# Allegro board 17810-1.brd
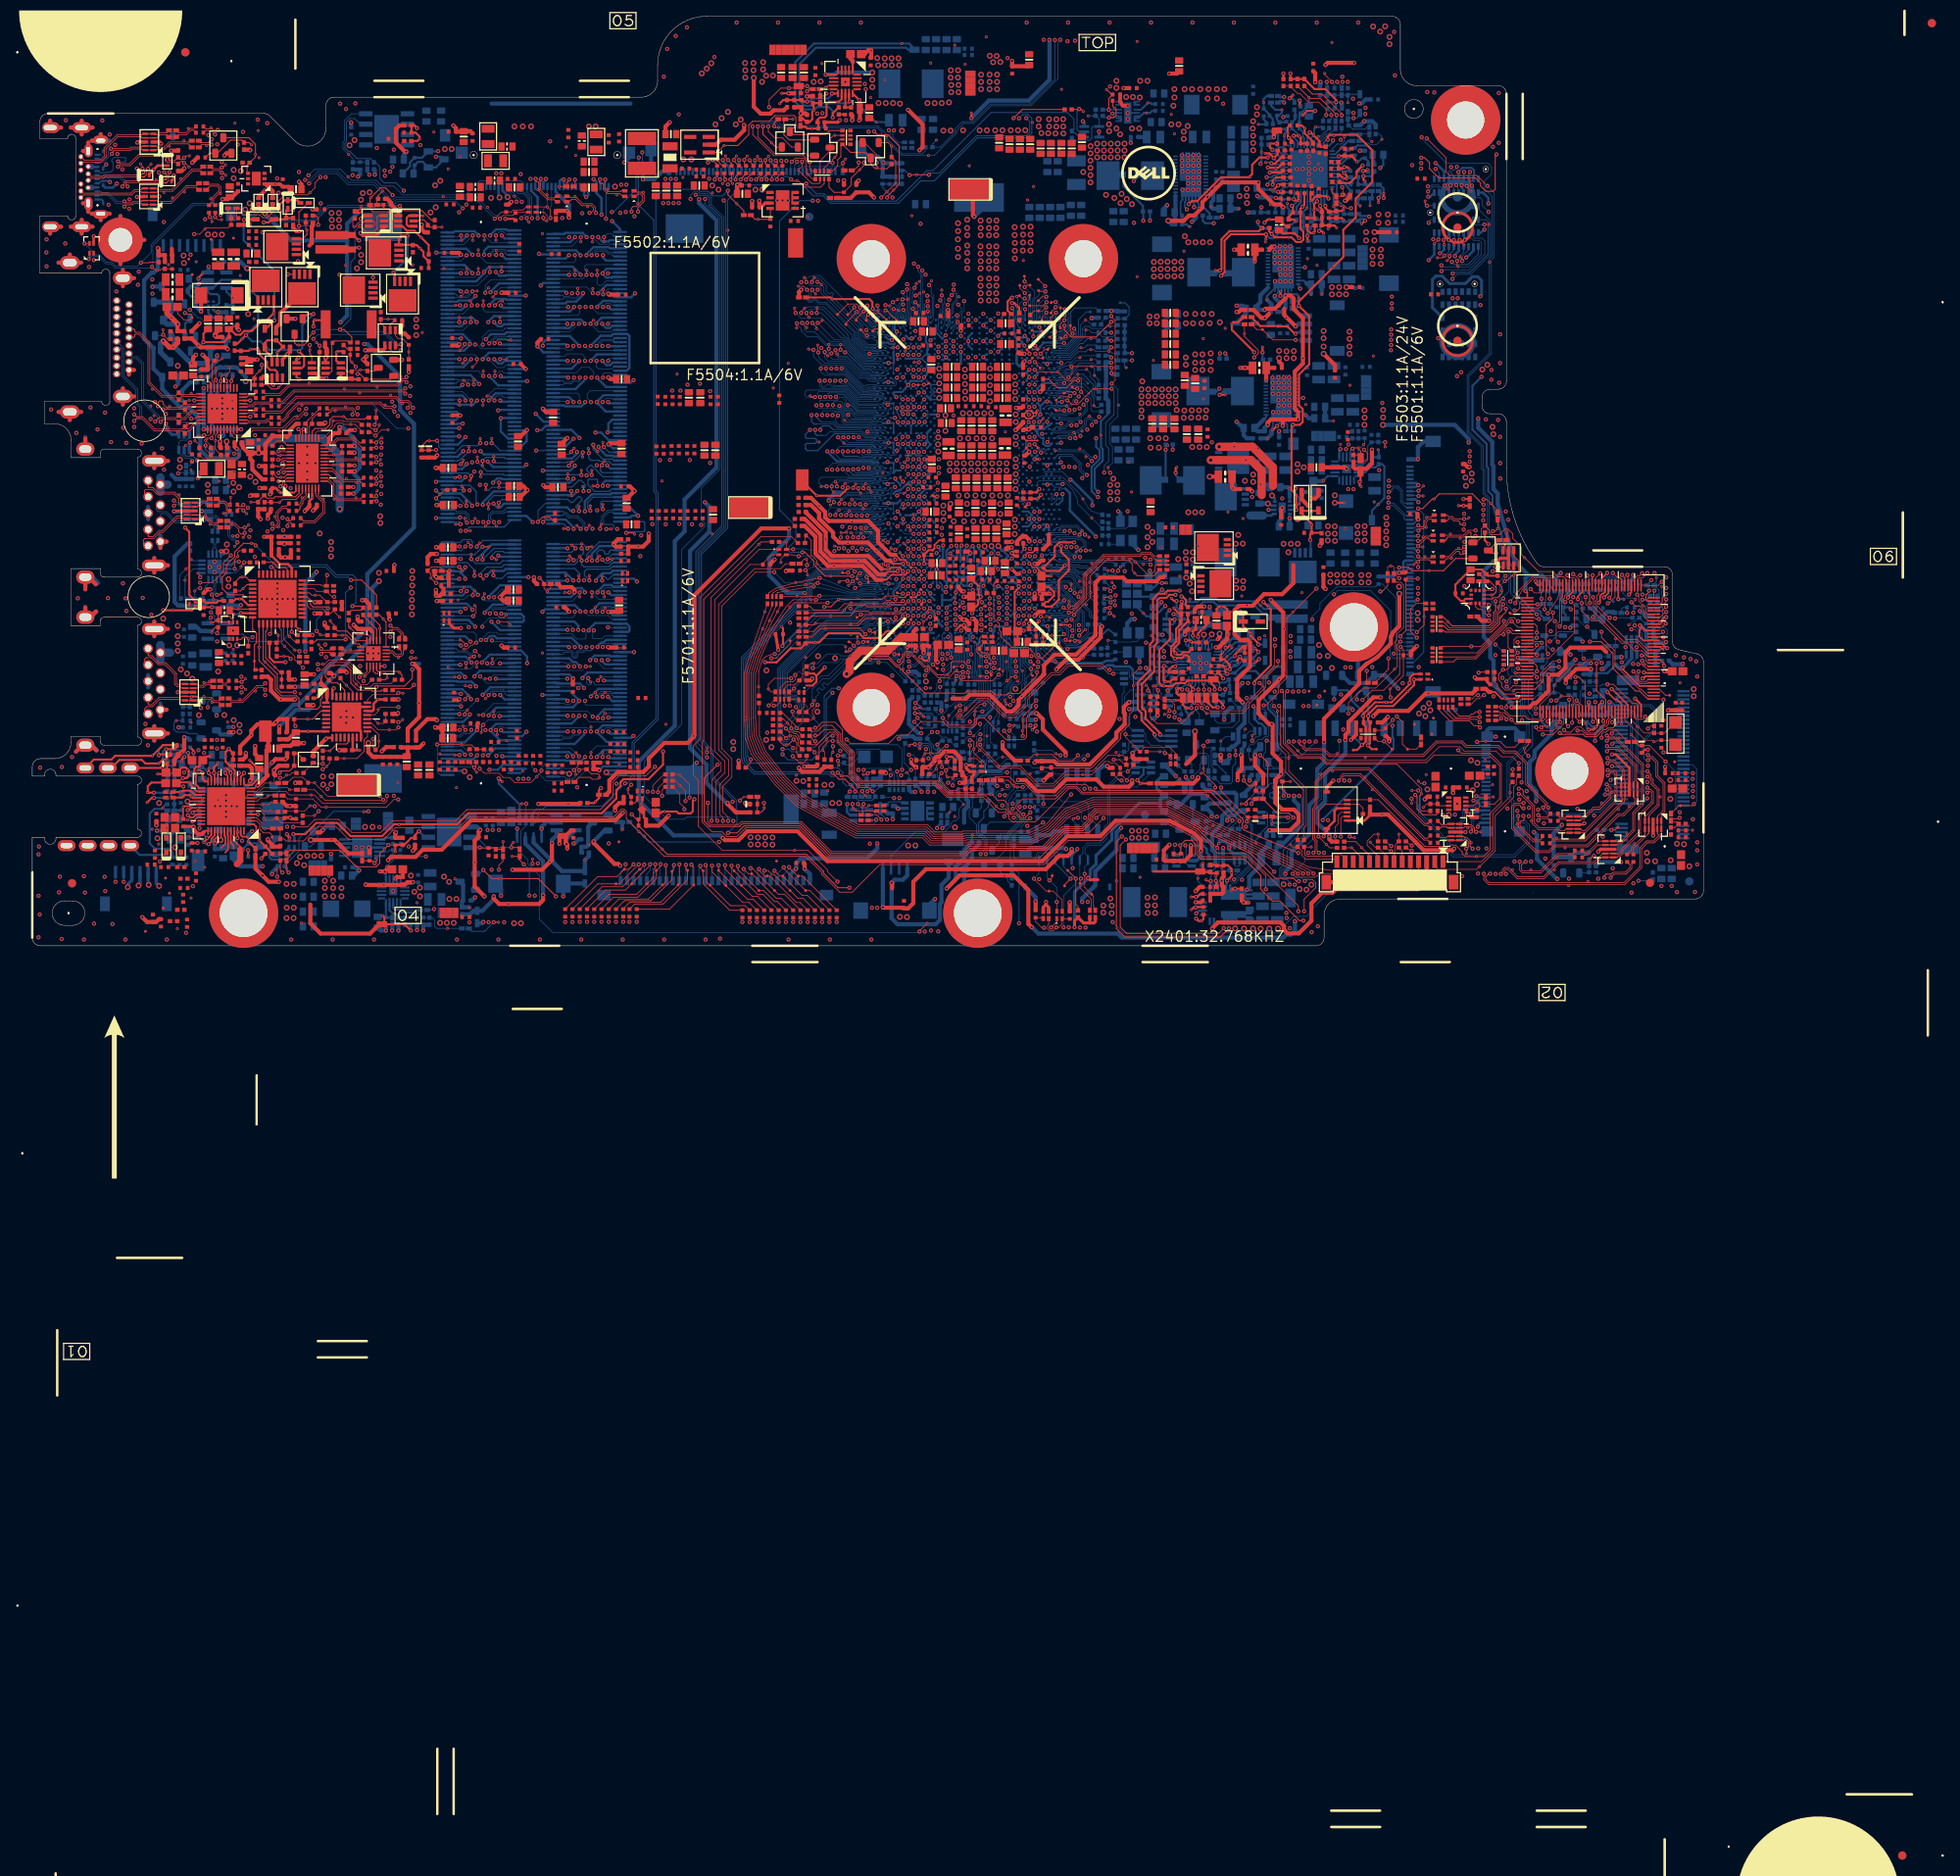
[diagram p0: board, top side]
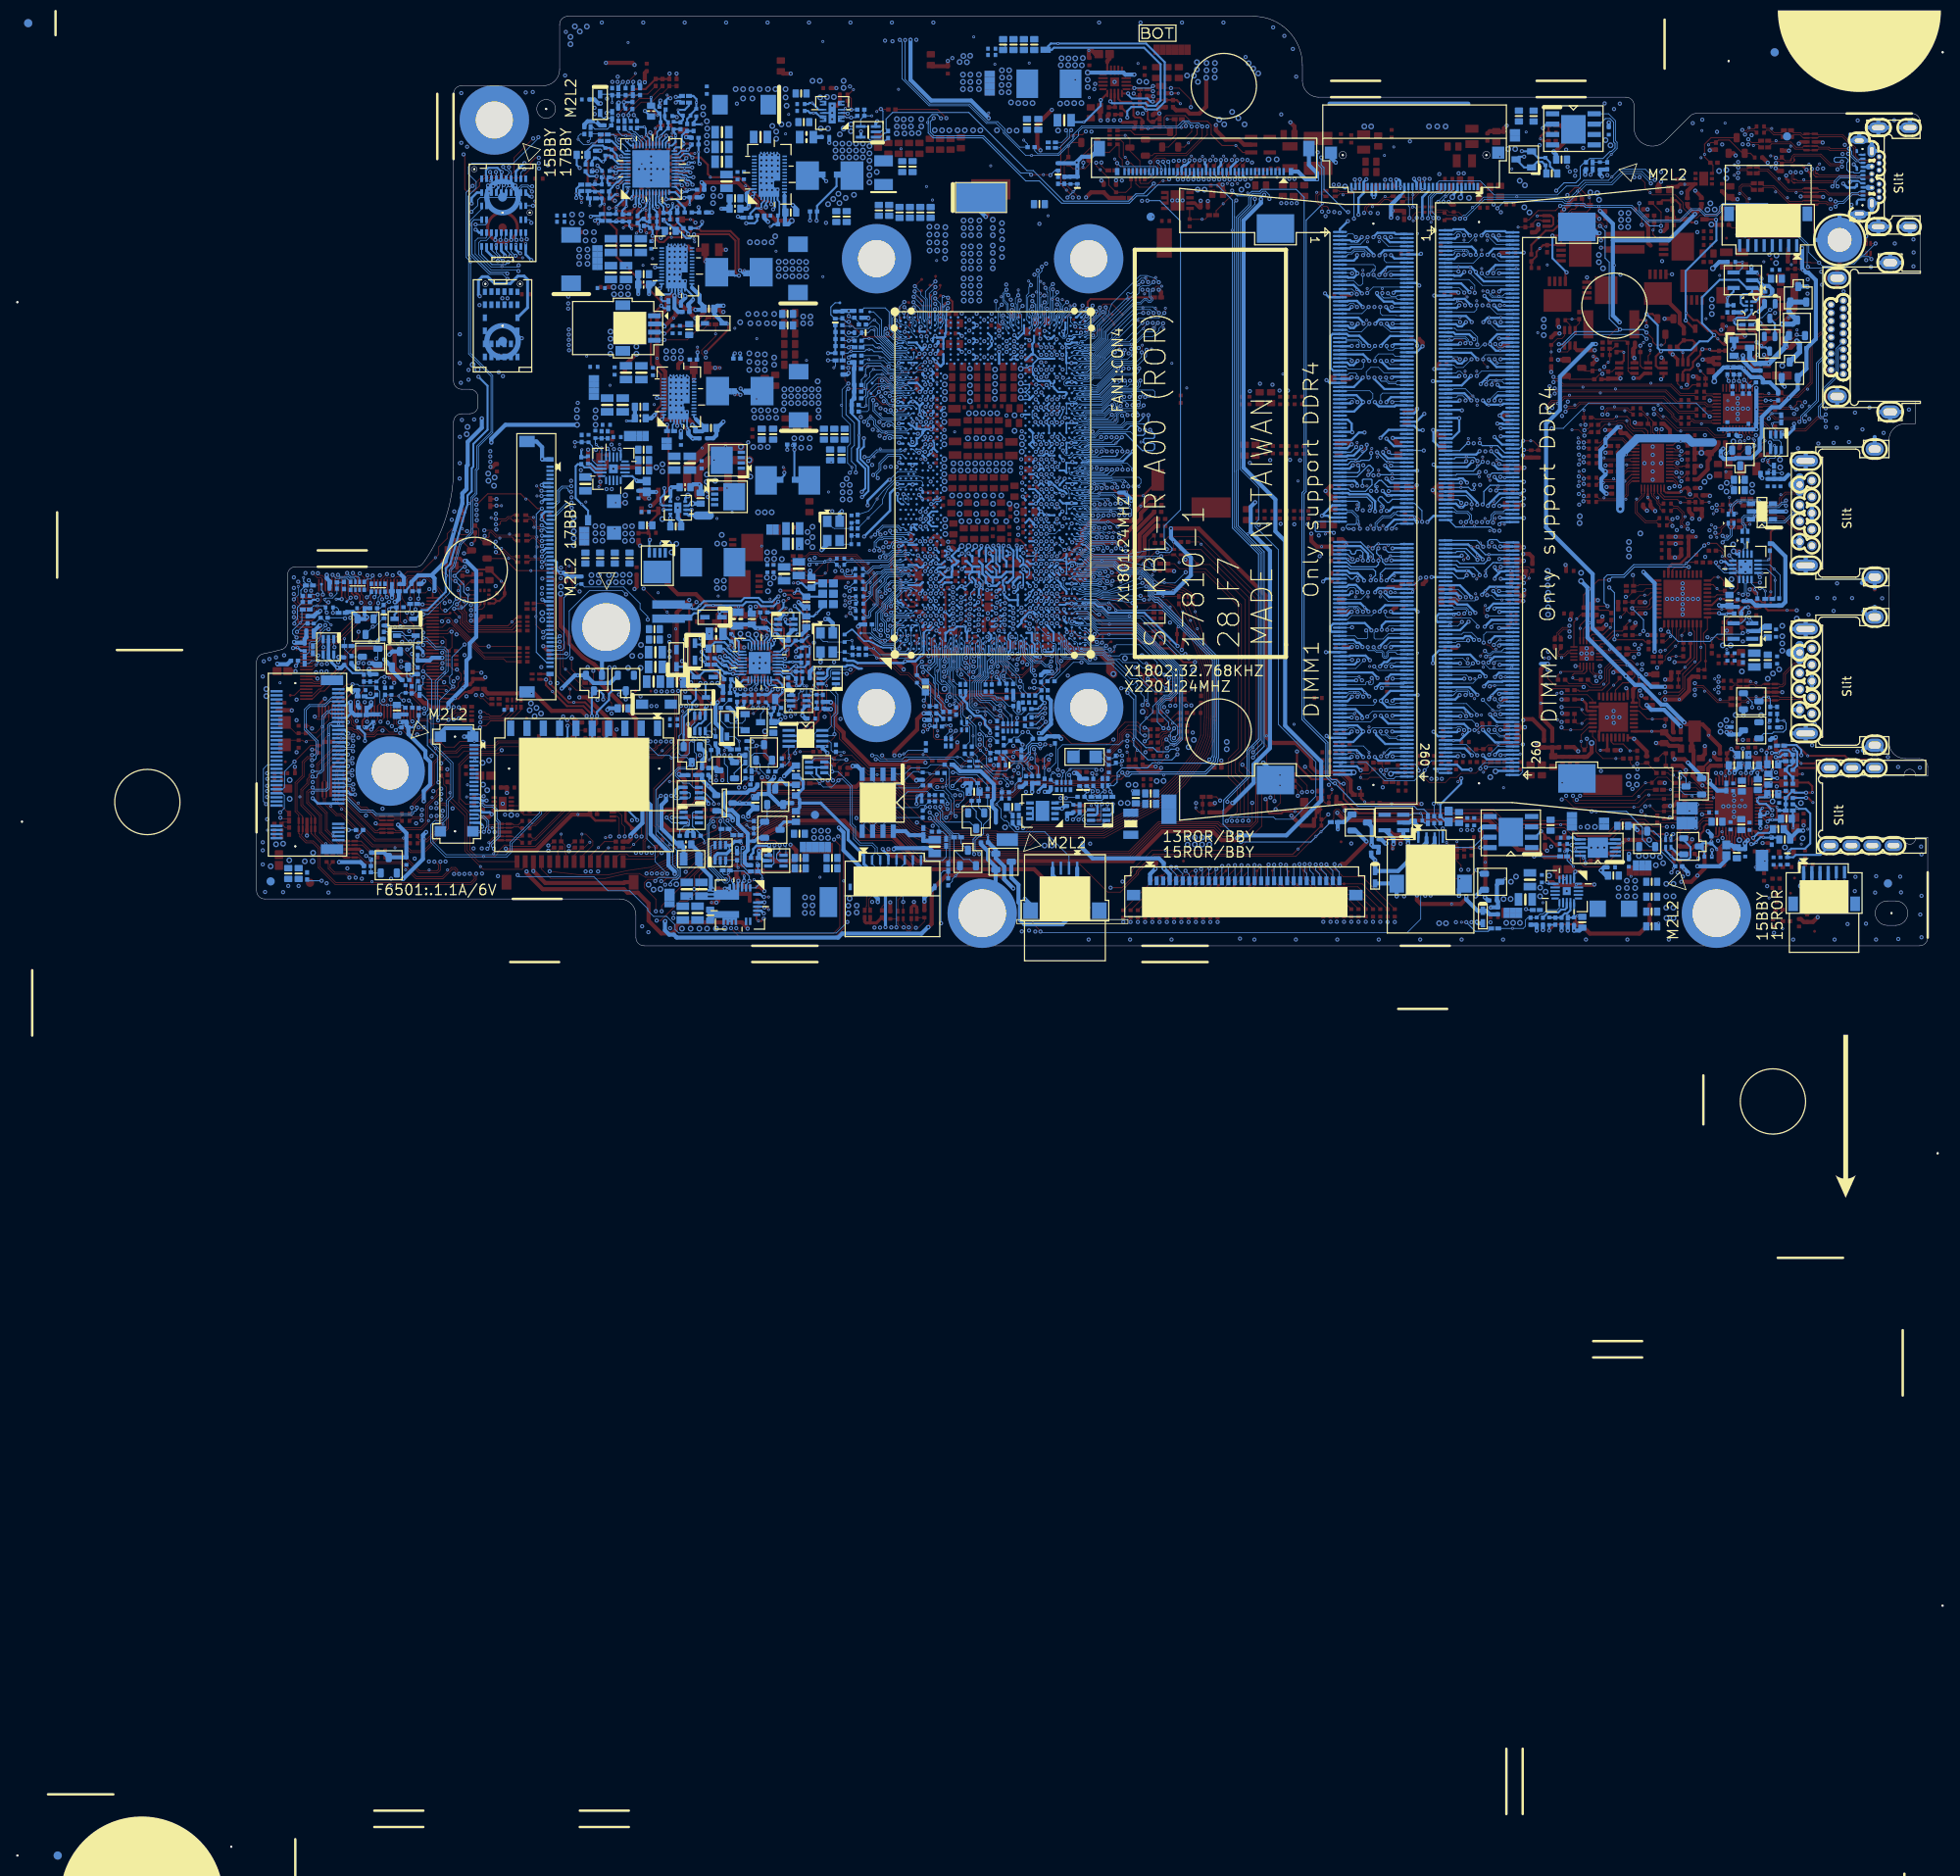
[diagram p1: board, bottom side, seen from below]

Outline 204.85 x 113.92 mm; copper layers: TOP, L2GND, L3, L4, L5VCC, L6, L7GND, BOTTOM. Coordinates in mm from the lower left corner of the outline.

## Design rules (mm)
constraint set DEFAULT: min track width 0.127, pair gap 0.102
net group CLK_50-MWS: nets SUS_CLK SUSCLK
net group CPU_RXN_C_DGPU_TXN0-DIFF1: nets CPU_RXN_C_DGPU_TXN0 CPU_RXP_C_DGPU_TXP0
net group CPU_RXN_C_DGPU_TXN1-DIFF1: nets CPU_RXN_C_DGPU_TXN1 CPU_RXP_C_DGPU_TXP1
net group CPU_RXN_C_DGPU_TXN2-DIFF1: nets CPU_RXN_C_DGPU_TXN2 CPU_RXP_C_DGPU_TXP2
net group CPU_RXN_C_DGPU_TXN3-DIFF1: nets CPU_RXN_C_DGPU_TXN3 CPU_RXP_C_DGPU_TXP3
net group DDR4_VREF_40: nets V_SM_VREF_CNTA V_SM_VREF_CNTB
net group DGPU_RXN_C_CPU_TXN0: nets DGPU_RXN_C_CPU_TXN0 PEG_TX_CPU_N0
net group DGPU_RXN_C_CPU_TXN1: nets DGPU_RXN_C_CPU_TXN1 PEG_TX_CPU_N1
net group DGPU_RXN_C_CPU_TXN2: nets DGPU_RXN_C_CPU_TXN2 PEG_TX_CPU_N2
net group DGPU_RXN_C_CPU_TXN3: nets DGPU_RXN_C_CPU_TXN3 PEG_TX_CPU_N3
net group DGPU_RXP_C_CPU_TXP0: nets DGPU_RXP_C_CPU_TXP0 PEG_TX_CPU_P0
net group DGPU_RXP_C_CPU_TXP1: nets DGPU_RXP_C_CPU_TXP1 PEG_TX_CPU_P1
net group DGPU_RXP_C_CPU_TXP2: nets DGPU_RXP_C_CPU_TXP2 PEG_TX_CPU_P2
net group DGPU_RXP_C_CPU_TXP3: nets DGPU_RXP_C_CPU_TXP3 PEG_TX_CPU_P3
net group EDP_AUX: nets EDP_AUX EDP_AUX_DP
net group EDP_AUX#: nets EDP_AUX# EDP_AUX_DN
net group ESPI_CLK: nets ESPI_CLK PCH_ESPI_CLK
net group ESPI_IO0: nets ESPI_IO0 PCH_ESPI_IO0
net group ESPI_IO1: nets ESPI_IO1 PCH_ESPI_IO1
net group ESPI_IO2: nets ESPI_IO2 PCH_ESPI_IO2
net group ESPI_IO3: nets ESPI_IO3 PCH_ESPI_IO3
net group FAN_TACH: nets FAN1_TACH FAN_TACH1_C
net group GPU_THM_SMBCLK: nets GPU_THM_SMBCLK THM_SML1_CLK
net group GPU_THM_SMBDAT: nets GPU_THM_SMBDAT THM_SML1_DATA
net group HDA_CODEC_SYNC: nets HDA_CODEC_SYNC HDA_SYNC
net group HDMI_CLK: nets HDMI_CLK HDMI_CLK_R
net group HDMI_CLK#: nets HDMI_CLK# HDMI_CLK#_R
net group HDMI_DATA0: nets HDMI_DATA0 HDMI_DATA0_R
net group HDMI_DATA0#: nets HDMI_DATA0# HDMI_DATA0#_R
net group HDMI_DATA1: nets HDMI_DATA1 HDMI_DATA1_R
net group HDMI_DATA1#: nets HDMI_DATA1# HDMI_DATA1#_R
net group HDMI_DATA2: nets HDMI_DATA2 HDMI_DATA2_R
net group HDMI_DATA2#: nets HDMI_DATA2# HDMI_DATA2#_R
net group I2C0_SCL_R: nets I2C0_SCL_R I2C0_SCL_TCH_PAD
net group I2C0_SDA_R: nets I2C0_SDA_R I2C0_SDA_TCH_PAD
net group MEM_SMBCLK: nets MEM_SMBCLK PCH_SMBCLK
net group MEM_SMBDATA: nets MEM_SMBDATA PCH_SMBDATA
net group MUX_TYPEC_TXN1: nets MUX_TYPEC_TXN1 MUX_TYPEC_TXN1_C
net group MUX_TYPEC_TXN2: nets MUX_TYPEC_TXN2 MUX_TYPEC_TXN2_C
net group MUX_TYPEC_TXP1: nets MUX_TYPEC_TXP1 MUX_TYPEC_TXP1_C
net group MUX_TYPEC_TXP2: nets MUX_TYPEC_TXP2 MUX_TYPEC_TXP2_C
net group PCH_DPC_N0: nets PCH_DPC_N0 PCH_DPC_N0_C
net group PCH_DPC_N1: nets PCH_DPC_N1 PCH_DPC_N1_C
net group PCH_DPC_N2: nets PCH_DPC_N2 PCH_DPC_N2_C
net group PCH_DPC_N3: nets PCH_DPC_N3 PCH_DPC_N3_C
net group PCH_DPC_P0: nets PCH_DPC_P0 PCH_DPC_P0_C
net group PCH_DPC_P1: nets PCH_DPC_P1 PCH_DPC_P1_C
net group PCH_DPC_P2: nets PCH_DPC_P2 PCH_DPC_P2_C
net group PCH_DPC_P3: nets PCH_DPC_P3 PCH_DPC_P3_C
net group PCIE_RCOMP-DIFF: nets PCIE_RCOMPN PCIE_RCOMPP
net group PCIE_TX_CPU_N6: nets PCIE_TX_CPU_N6 PCIE_TX_WLAN_N6
net group PCIE_TX_CPU_N9: nets PCIE_TX_CPU_N9 PCIE_TX_CPU_N9_C
net group PCIE_TX_CPU_N10: nets PCIE_TX_CPU_N10 PCIE_TX_CPU_N10_C
net group PCIE_TX_CPU_N11: nets PCIE_TX_CPU_N11 PCIE_TX_CPU_N11_C
net group PCIE_TX_CPU_P6: nets PCIE_TX_CPU_P6 PCIE_TX_WLAN_P6
net group PCIE_TX_CPU_P9: nets PCIE_TX_CPU_P9 PCIE_TX_CPU_P9_C
net group PCIE_TX_CPU_P10: nets PCIE_TX_CPU_P10 PCIE_TX_CPU_P10_C
net group PCIE_TX_CPU_P11: nets PCIE_TX_CPU_P11 PCIE_TX_CPU_P11_C
net group PEG_CLK_CPU0-DIFF1: nets CLK_PCIE_VGA CLK_PCIE_VGA#
net group PEG_CLK_CPU1-DIFF221: nets PEG_CLK1_CPU PEG_CLK1_CPU#
net group POWER_120MIL: nets +1.8VALW_EC +VCCSTG
net group SATA_TX_CPU_N12: nets SATA_TX_CPU_N12 SATA_TX_CPU_N12_C
net group SATA_TX_CPU_P12: nets SATA_TX_CPU_P12 SATA_TX_CPU_P12_C
net group SIGNAL_V_F_8_OHM-MW: nets CFG3 XDP_DBRESET#
net group SIGNAL_V_F_16.5_SVID-MWS: nets VR_SVID_CLK VR_SVID_DATA
net group SPI_CS_CPU_N0: nets SPI_CS_CPU_N0 SPI_CS_ROM_N0
net group USB30_RX_C2-DIFF242: nets USB30_RXDN2_C USB30_RXDP2_C
net group USB30_RX_CPU_N4: nets USB30_RX_CPU_N4 USB30_RX_CPU_N4_C
net group USB30_RX_CPU_P4: nets USB30_RX_CPU_P4 USB30_RX_CPU_P4_C
net group USB30_TX_CPU_N4: nets USB30_TX_CPU_N4 USB30_TX_CPU_N4_C
net group USB30_TX_CPU_P4: nets USB30_TX_CPU_P4 USB30_TX_CPU_P4_C
net group USB30_TXDN1_R: nets USB30_TX_CPU_N1 USB30_TXDN1_R
net group USB30_TXDN2_R: nets USB30_TX_CPU_N2 USB30_TXDN2_R
net group USB30_TXDP1_R: nets USB30_TX_CPU_P1 USB30_TXDP1_R
net group USB30_TXDP2_R: nets USB30_TX_CPU_P2 USB30_TXDP2_R
net group USB_CPU_PN0: nets USB_CPU_PN0 USB_PN0_R
net group USB_CPU_PP0: nets USB_CPU_PP0 USB_PP0_R
net group XDP_TCLK-MWS: nets XDP_TCK_JTAGX XDP_TCLK
net group XTAL24_IN: nets XTAL24_IN XTAL24_IN_R
net group XTAL24_IN_U42: nets XTAL24_IN_U42 XTAL24_IN_U42_R
net group XTAL24_OUT: nets XTAL24_OUT XTAL24_OUT_R
net group XTAL24_OUT_U42: nets XTAL24_OUT_U42 XTAL24_OUT_U42_R
net group XTAL-MW: nets MEC_XTAL1_R MEC_XTAL2
net group 3.5: nets CFG12 CFG14 M_A_DQS_DN0 M_A_DQS_DN1 M_A_DQS_DN2 M_A_DQS_DN3 M_A_DQS_DN4 M_A_DQS_DN5 M_A_DQS_DN6 M_A_DQS_DN7 M_A_DQS_DP0 M_A_DQS_DP1 M_A_DQS_DP2 M_A_DQS_DP3 M_A_DQS_DP4 M_A_DQS_DP5 M_A_DQS_DP6 M_A_DQS_DP7 M_B_DQS_DN1 M_B_DQS_DP1 USB_CPU_PN2 USB_CPU_PN4 USB_CPU_PN6 USB_CPU_PP2 USB_CPU_PP4 USB_CPU_PP6 VCCGT_SENSE VSSGT_SENSE
net group AUDIO_12MIL: nets CPVEE
net group AUDIO_BEEP_10MIL: nets AUD_HP1_JACK_L AUD_HP1_JACK_L1 AUD_HP1_JACK_R AUD_HP1_JACK_R1 AUD_PC_BEEP AUD_PC_BEEP_C AUD_PC_BEEP_R AUD_PORTA_L_R_B AUD_PORTA_R_R_B AUD_SENSE AUD_SENSE_A AUD_VREF CBN CBP HDA_SPKR_R JACK_PLUG JACK_PLUG_DET KBC_BEEP_R LINE1-L_C LINE1-L_R LINE1_L LINE1_R LINE1_VREFO_L LINE1_VREFO_R MIC2_VREFO_L MIC2_VREFO_R SPKR
net group AUDIO_DIGITAL_50-MWS: nets HDA_RST#
net group BOT_MUX_N: nets BOT_MUX_N_L
net group BOT_MUX_P: nets BOT_MUX_P_L
net group CCG4_MUX: nets 5V_VCONN_EN 5V_VCONN_P1 5V_VCONN_P1_CCG4 CCG4_FLIP# CCG4_OVP_TRIP_P1 CCG4_OVP_TRIP_P1_G DOCK_USB_EN_A DOCK_USB_EN_B MUX_ENA_L MUX_ENB_L MUX_INB_N MUX_INB_P MUX_SAI MUX_SAO MUX_SBI MUX_SBO VCONN_MON_P1
net group CFG_50-MWS: nets CFG0 CFG1 CFG2 CFG4 CFG5 CFG6 CFG7 CFG8 CFG9 CFG10 CFG11 CFG13 CFG15 CFG16 CFG17 CFG18 CFG19
net group CODEC_BITCLK_R: nets CODEC_BITCLK_R HDA_BITCLK HDA_CODEC_BITCLK
net group CODEC_SDOUT_R: nets CODEC_SDOUT_R HDA_CODEC_SDOUT HDA_SDOUT
net group COMP_20MIL: nets CPU_POPIRCOMP CSI2_COMP EMMC_RCOMP EOPIO_RCOMP PCH_POPIRCOMP SD_RCOMP SM_RCOMP_0 SM_RCOMP_1 SM_RCOMP_2 USBCOMP
net group CPU_50-MWS: nets H_PROCHOT#_R PQ4405_3 PWR_CHG_PROCHOT#
net group DDR4_A_CMD_40-MW: nets M_A_ALERT_N
net group DDR4_B_CMD_40--MW: nets M_B_ALERT_N
net group DPB_AUXN: nets DPB_AUXN_C
net group DPB_AUXP: nets DPB_AUXP_C
net group EDP_TX0: nets EDP_TX0
net group EDP_TX0#: nets EDP_TX0#
net group EDP_TX1: nets EDP_TX1
net group EDP_TX1#: nets EDP_TX1#
net group EDP_TX2: nets EDP_TX2
net group EDP_TX2#: nets EDP_TX2#
net group EDP_TX3: nets EDP_TX3
net group EDP_TX3#: nets EDP_TX3#
net group GND: nets MIC_GND
net group HDA_CODEC_SDIN0: nets HDA_CODEC_SDIN0
net group JTAG-MW: nets PCH_JTAG_TCK PCH_JTAG_TDI PCH_JTAG_TDO PCH_JTAG_TMS
net group KBC: nets KSI0 KSI1 KSI2 KSI3 KSI4 KSI5 KSI6 KSI7 KSO0 KSO1 KSO2 KSO3 KSO4 KSO5 KSO6 KSO7 KSO8 KSO9 KSO10 KSO11 KSO12 KSO13 KSO14 KSO15 KSO16
net group LCD_BKLT: nets BKLT_CTRL BKLT_EN_EC L_BKLT_CTRL L_BKLT_EN_EC LCD_BRIGHTNESS
net group LED: nets BAT1_LED# BAT2_LED# BATT_WHITE_LED# BATT_WHITE_LED_R# CAP_LED# CAP_LED_R# CHG_AMBER_LED#
net group LED_20MIL: nets AMBER_LED_BAT BAT_AMBER BAT_WHITE CAP_LED#_R CAP_LED_Q CHG_AMBER_LED_R# WHITE_LED_BAT
net group LPC-MWS: nets CLKRUN# CLKRUN#_EC ESPI_ALERT# ESPI_ALERT#_ESPI ESPI_CLK_C ESPI_IO0_C ESPI_IO1_C ESPI_IO2_C ESPI_IO3_C GPP_A10/CLKOUT_LPC1 LID_CL_SIO_TAB#
net group OTHER_4MIL: nets 1D8V_ESPI 3D_CAM_DET# A5_TP A67_TP A70_TP AD_IA AUX_EN_WOWL BLON_OUT BLON_OUT_C BLUETOOTH_EN BOARD_ID BOARD_ID1 BOARD_ID2 CAM_EN# CCG4_ID_1 CCG4_ID_2 CFG CLK_PCIE_LAN_REQ# CLK_PCIE_NVME_REQ# CLK_PCIE_PEG_REQ# CLK_PCIE_SD_REQ# CLK_PCIE_TBT_REQ# CLK_PCIE_WLAN_REQ# CMP_VIN1 COMBO-GPI CPU_DP1_HPD CPU_DP_HPD_MUX CTL1 CTL2 CTL3 DBC_EN_R DBC_PANEL_EN DCIN_EN DDCBUF DGPU_PWR_EN DGPU_PWROK DMIC_PCH_CLK DVSS EAPD# EDP_DISP_UTIL EDP_HPD EDP_HPD_CONN EQ FALL_INT2 FAN_PWM1_C FFS_INT2 FFS_INT2_Q FFS_INT2_Q_R GPD11/LANPHYPC GPIO052/SPI_IO2 GPP_E0/SATAXPCIE0/SATAGP0 GPP_E1/SATAXPCIE1/SATAGP1 GPU_PWR_LEVEL GSEN2_INT1_ISH GSEN2_INT2 GSEN2_INT2_ISH GSEN_INT1 GSEN_INT1_ISH GSEN_INT2 GSEN_INT2_ISH GYRO_DRDY_ISH GYRO_INT GYRO_INT_C GYRO_INT_ISH GYRO_INT_P11 H_CATERR# HDD_CT HDD_DET# HDD_DEVSLP_R HDD_EN HDD_EN_PCH HDMI_EC_DET# HDMI_EC_DET#_C HOST_DEBUG_TX HOST_DEBUG_TX_CON HPD_HDMI_CON HPD_HDMI_CON_C I2C0_SCL_TCH_PNL I2C0_SDA_TCH_PNL I_ADP_R ICSP_CLR IE_DELAY_G IE_DELAY_S ILIM_HI ILIM_LO ILIM_SEL INT2_SELECT INT#_TYPEC_R IR_CAM_DET# IR_CAMERA_DET#_R ISET ISH_KB_DISABLE ISH_KB_DISABLE_R KB_CLOSE#_2 KB_LED_BL_DET KB_LED_DET_C KBC_PWRBTN# L_BKLT_EN L_BKLT_EN_C LANWAKE# LCD_TST_C ME_FWP_EC MEM_CHB_EN MEM_CONFIG0 MODEL_ID MSATA_DEVSLP_R MSM# NB_MODE# NB_MUTE# NRB_BIT OVER_CURRENT_P8# P_SYS PBAT_PRES1# PBAT_PRES# PCH_BATLOW# PCH_THERMTRIP# PCH_WAKE# PCIE_WAKE# PD4403_A PD4403_K PD_VBUS_C_CTRL1_R PIRQA# PME# POWER_SW_IN# PQ4405_2 PQ4405_5 PQ4405_6 PQ4408_C PQ4408_E PRE PROC_SELECT# PROJECT_ID0 PROJECT_ID1 PROJECT_ID2 PROJECT_ID3 PS_ID_R PS_ID_R1 PSYS PWR_1D2V_EN PWR_2D5V_EN PWR_CHG_ACOK REXT SA0_CHA_DIM0 SA0_CHB_DIM0 SA1_CHA_DIM0 SA1_CHB_DIM0 SA2_CHA_DIM0 SA2_CHB_DIM0 SD_READ_MODE SERIRQ_TPM SIO_EXT_SMI# SIO_EXT_WAKE# SIO_PWRBTN# SIO_SLP_A# SIO_SLP_S5# SKTOCC# SLP_SUS# SM_INTRUDER# SMB_ALERT# SML0_ALERT# SML1ALERT# SPI_IRQ#_TPM2 SPK_ID SSD_DEVSLP SYS_PRES1# SYSPWR_PRES TOUCH_PAD_INTR# TOUCH_PANEL_PD# TP_WAKE_KBC# TPM_ID TPM_SPI_IRQ# USB2_ID USB2_VBUSSENSE USB_OC1# USB_OC2# USB_POWERSHARE_VBUS_EN USB_PWR_SHR_EN_L# VBUS_PRODECT# VCREF0 VOL_DOWN# VOL_UP# VR_RDY VRALERT# VRAM_ID1 VRAM_ID2 WIFI_RF_EN ZVM#
net group PECI-MW: nets H_PECI_CPU
net group PLATFORM: nets 1D0V_S5_PWRGD 1D8V_EN# 1D8V_EN_R# 1D8V_S5_PWROK 3D3V_S0_ON 3V5V_S0_ON 3V_5V_POK# 3V_5V_POK_C 5V_S0_ON +SDC_IN_SW +SDC_IN_SW_R1 CAD_SNK CPU_DP2_HPD CPU_DP_HPD CPU_DP_HPD_R DGPU_HOLD_RST# DPEQ0_A1 DPEQ1 EDP_VDD_EN EQ0 EQ1 GC6_FB_EN_MCP GPU_EVENT# GPU_EVENT_MCP# GSENSOR_CS GSENSOR_SDO H_CPUPWRGD H_VCCST_PWRGD HPDIN I2CEN IC_DELAY INT#_TYPEC LVDS_VDD_EN_R M2_SSD_PEDET ME_SUS_PWR_ACK_R PCH_PLTRST# PCH_RSMRST# PD_SWD_CLK PD_SWD_IO PD_VBUS_C_CTRL1 PD_VBUS_C_CTRL1_A PD_VBUS_DISCHG PD_VBUS_P_CTRL1 PD_VBUS_P_CTRL1_R PD_VBUS_R PD_VCCD PD_XRES PM_RSMRST#_M PM_RSMRST#_R PTP_DIS#_R PWR_0D6V_S3EN PWR_0D6V_S5EN PWR_0D6V_VCNTL PWR_1D0V_EN PWR_1D0V_PG PWR_1D5V_EN PWR_1D8V_EN PWR_1D8V_POK PWR_2D5V_PG PWR_3D3V_EN PWR_3D3V_EN1 PWR_3V_PG PWR_5V_PG PWR_VCORE_EN RSMRST_PWRGD# RTCRST_ON SATA_LED# SLP_LAN# SM_DRAMRST# SM_PGCNTL SM_PGCNTL_R SRTC_RST# SSD_PEDET SSEQ0_A0 SSEQ1 SUSACK#_R TP_ON#_GATE TPS70933_EN TPS70933_EN_G TS#_DIMM0_1 TS#_DIMM1_1 USB_ADT_SW USB_ADT_SW_R USB_EN# USB_TYPEC_R VCCSTG_EN_R VCCSTU_EN_R
net group POWER_10M: nets 1.8V_RUN_FB 3V5V_CT1 3V5V_CT2 5V_STB +3V_1D8V_AVDD +VCCAMPHYPLL_1P0 +VCCAPLL_1P0 +VCCCLK2 +VCCCLK4 +VCCCLK5 +VCCCOREG0 +VCCCOREG1 +VCCDSW_1P0 +VCCFUSEPRG +VCCPAZIO +VCCPDSW_3P3 +VCCPRTC_3P3 +VCCSFR +VCCST_CPU +VDDQ_CPU_CLK BOOST_MON I_BATT LDO1_CAP LDO2_CAP LDO3_CAP MIC_CAP PWR_1D0V_BT PWR_1D0V_FB PWR_1D0V_FB_A PWR_1D0V_PFM PWR_1D0V_SS PWR_1D0V_TON PWR_1D2V_BYP PWR_1D2V_IMAX PWR_1D2V_VFB PWR_1D2V_VFB_R PWR_2D5V_FB PWR_3D3V_FB PWR_3D3V_VOUT PWR_5V_EN PWR_5V_EN1 PWR_5V_EN1_R PWR_5V_FB PWR_5V_FB_A PWR_5V_LDO PWR_5V_VOUT PWR_VCCGT_COMP PWR_VCCGT_COMP_R PWR_VCCGT_CSCOMP PWR_VCCGT_CSN PWR_VCCGT_CSN_L PWR_VCCGT_CSP PWR_VCCGT_CSP1 PWR_VCCGT_CSP2 PWR_VCCGT_CSREF PWR_VCCGT_CSSUM PWR_VCCGT_DIFFOUT PWR_VCCGT_FB PWR_VCCGT_FB_R PWR_VCCGT_ICCMAX PWR_VCCGT_ILIM PWR_VCCGT_ILIM_R PWR_VCCGT_IOUT PWR_VCCGT_NTC PWR_VCCGT_PWMA PWR_VCCGT_TSENSE PWR_VCCGT_VCCA PWR_VCCGT_VSN PWR_VCCGT_VSN_R PWR_VCCGT_VSP PWR_VCCSA_COMP PWR_VCCSA_COMP_R PWR_VCCSA_CSN PWR_VCCSA_CSN_L PWR_VCCSA_CSN_NTC PWR_VCCSA_CSP PWR_VCCSA_CSP1B PWR_VCCSA_ICCMAX PWR_VCCSA_ILIM PWR_VCCSA_IOUT PWR_VCCSA_VSN PWR_VCCSA_VSN_R PWR_VCCSA_VSP PWR_VCCSA_VSP_R PWR_VCCSA_VSP_RC PWR_VCORE_COMP PWR_VCORE_COMP_R PWR_VCORE_CSNA PWR_VCORE_CSNB PWR_VCORE_CSNNTC PWR_VCORE_CSP_1A PWR_VCORE_CSPA PWR_VCORE_CSPB PWR_VCORE_DRVON PWR_VCORE_ICCMAX PWR_VCORE_ILIM PWR_VCORE_IOUT PWR_VCORE_NTC PWR_VCORE_PWM1 PWR_VCORE_PWM2 PWR_VCORE_ROSC_COREGT PWR_VCORE_ROSC_SAUS PWR_VCORE_TSENSE PWR_VCORE_VCC_R PWR_VCORE_VR_RDY PWR_VCORE_VRHOT# PWR_VCORE_VRMP PWR_VCORE_VSN PWR_VCORE_VSN_R PWR_VCORE_VSP PWR_VCORE_VSP_R PWR_VCORE_VSP_RC Q6204_G TYPEC_5V TYPEC_5V_L TYPEC_5V_SW_R USB_TYPEC_DIS V0.85A_VID0 V0.85A_VID1 VCCRTCEXT
net group POWER_10M_POWER: nets AC_IN#_G ACLIM AD_OFF_L AD_OFF_R PR_2 PWR_3D3V_FB2 PWR_ASGATE PWR_CHG_1 PWR_CHG_ACDET PWR_CHG_BATDRV PWR_CHG_BATPRES# PWR_CHG_BTST1 PWR_CHG_COMP PWR_CHG_FSET PWR_CHG_IADP PWR_CHG_IDCHG PWR_CHG_ILIM PWR_CHG_NTC PWR_CHG_PMON PWR_CHG_PROG PWR_CHG_REGN PWR_CHG_SRN_1 PWR_CHG_SRP_1 PWR_CMSRC PWR_OPCN PWR_OPCP PWR_VBAT PWR_VCCSA_PWM PWR_VCORE_ADDR_BOOT USB_ADT_D USB_ADT_D1 USB_ADT_R1 USB_TYPEC_SW VDD VSS_AY71
net group POWER_15M: nets Q6205_Q Q6502_D TP_VDD
net group POWER_20M: nets 1D8V_S0 3D3V_AUX_S5 3D3V_RTC_SYS 3D3V_SPIVCC1 5V_AUX_S5 +5V_AVDD +RTC_VCC +V_VREF_PATH1 +V_VREF_PATH2 ECVBAT PWR_1D2V_BOOT PWR_1D2V_BOOT_R PWR_3D3V_BOOT PWR_3D3V_BOOT_A PWR_5V_BOOT PWR_5V_BOOT_A PWR_VCCGT_SNUB_1 PWR_VCORE_SNUB1 PWR_VCORE_SNUB2 VCC3PD VDDIO VREF_CPU VREG3PD
net group POWER_20M_POWER: nets +5V_KB_BL KB_BL_CTRL# KB_LED_PWM PWR_CHG_VCC PWR_VCCGT_BOOTA PWR_VCCGT_BOOTA_RC PWR_VCCSA_BST PWR_VCCSA_BST_RC PWR_VCCSA_SNUB PWR_VCORE_BOOT1 PWR_VCORE_BOOT2 PWR_VCORE_BOOT_RC1 PWR_VCORE_BOOT_RC2 PWR_VCORE_VCC1 PWR_VCORE_VCC2
net group POWER_25M: nets PQ3802_1 PS_ID_R2 PSID_DISABLE#_R_C
net group POWER_40M: nets 3D3V_TPM +UZ12_TPM DDR_VREF_S3 TPM_VDD14 TPM_VDD22 TPM_VSB
net group POWER_40M_POWER: nets 1D5V_PWR
net group POWER_2680M_POWER: nets U22_POWER_K52
net group PWR_DISB: nets PWR_VCCGT_DISB#_A PWR_VCORE_DISB#1 PWR_VCORE_DISB#2
net group REF10M: nets VR_CAP
net group SATA_RXN0_R: nets SATA_RX_CPU_N0
net group SATA_RXP0_R: nets SATA_RX_CPU_P0
net group SATA_TXN0_R: nets SATA_TX_CPU_N0
net group SATA_TXP0_R: nets SATA_TX_CPU_P0
net group SIGNAL_V_F_4MIL: nets 3V_5V_POK AC_DIS AC_DIS_R AC_PRESENT FAN1_PWM FFS_INT1 GPD2/LAN_WAKE# GSEN2_INT1 GSEN2_INT1_C GSEN2_INT2_C GYRO_DRDY HDD_DEVSLP ITP_PMODE KB_DET# LCD_TST LCD_VCC_TEST_EN LID_CL_SIO# MASK_SATA_LED# MSATA_RST# PLT_RST# PLT_RST#_Q_TPM2 RESET_OUT# RTC_DET# USB_OC0# USB_OC3# VR_EN
net group SIGNAL_V_F_5MIL: nets 1D2V_VTT_PWRGD 3V_5V_EN ACOK# ALWON BREATH_LED# DDR4_DRAMRST# EC_SLP_S0IX# EXT_PWR_GATE# GC6_FB_EN GC6_THM_DIS# GC6_THM_DIS#_EC PANEL_BKEN_EC PANEL_BKEN_EC_C PCH_DPWROK PM_PCH_PWROK PM_RSMRST# RTC_RST# RUNPWROK SIO_SLP_S0# SIO_SLP_S3# SIO_SLP_S4# SLP_S0_U SYS_PWROK TOUCH_PANEL_INTR# TOUCH_REPORT_SW TP_EN# TPM_GPIO0 TPM_GPIO2 TPM_GPIO4
net group SIGNAL_V_F_10MIL: nets BEEP FAN_TACH1 PD_CC1 PD_CC2 USBC1_CC1_CONN USBC1_CC2_CONN
net group SIGNAL_V_F_10MIL-2: nets ACOK_IN_M DC_IN_OK DC_IN_OK# DC_IN_OK_R HW_ACAV_IN HW_ACAVIN_NB
net group SIGNAL_V_F_14_OHM-MW: nets VR_SVID_ALERT#
net group SIGNAL_V_F_15_OHM-MW: nets H_PECI
net group SIGNAL_V_F_16.5_OHM-MWS: nets PCH_SPI_CS2# Q9102.G SPI_CLK_ROM_TPM2 SPI_CS2#_R SPI_CS2#_R_TPM2 SPI_SI_ROM_TPM2
net group SIGNAL_V_F_25MIL: nets PS_ID
net group SIGNAL_V_F_50_OHM-MWS: nets CCG4_I2C_SCL CCG4_I2C_SDA H_PROCHOT# PROCHOT
net group SMBUS_10MIL: nets PBAT_CHG_SMBCLK PBAT_CHG_SMBDAT PBAT_SMBCLK1 PBAT_SMBDAT1
net group SMBUS_50-MWS: nets CLK_TP_SIO CPU_DP2_CTRL_CLK CPU_DP2_CTRL_DATA DAT_TP_SIO DDC_CLK_HDMI DDC_CLK_PH1 DDC_DATA_HDMI DDC_DATA_PH2 DMIC_CLK DMIC_CLK_C DMIC_CLK_R DMIC_DATA DMIC_DATA_C DMIC_DATA_R I2C1_SCL I2C1_SDA I2C_CLK_PD I2C_CLK_PD_MUX I2C_DATA_PD I2C_DATA_PD_MUX ICSP_CLOCK ICSP_DATA ISH_I2C0_SCL ISH_I2C0_SDA PWR_CHG_SCL PWR_CHG_SDA SENSOR_I2C_SCL SENSOR_I2C_SCL_2G SENSOR_I2C_SDA SENSOR_I2C_SDA_2G SML0_SMBCLK SML0_SMBDATA TPCLK_C TPDATA_C TYPEC_SMBCLK TYPEC_SMBDA
net group SPI_50-MWS: nets SIO_EXT_SCI# SIO_RCIN# SPI_SO_ROM_TPM2
net group SPI_CLK_CPU: nets SPI_CLK_CPU SPI_CLK_ROM SPI_CLK_ROM_R
net group SPI_HOLD_CPU: nets SPI_HOLD_CPU SPI_HOLD_ROM SPI_HOLD_ROM_R
net group SPI_SI_CPU: nets SPI_SI_CPU SPI_SI_ROM SPI_SI_ROM_R
net group SPI_SO_CPU: nets SPI_SO_CPU SPI_SO_ROM SPI_SO_ROM_R
net group SPI_WP_CPU: nets SPI_WP_CPU SPI_WP_ROM SPI_WP_ROM_R
net group SVID-MW: nets H_CPU_SVIDALRT# H_CPU_SVIDCLK H_CPU_SVIDDAT PWR_VCORE_ALERT# PWR_VCORE_SCLK PWR_VCORE_SDIO
net group T8-MW: nets CMP_VIN0 CMP_VIN0_R CMP_VOUT0 VD_IN1_C
net group TESTPD_4MIL: nets AV1_TP AV71_TP B71_TP BA1_TP BA2_TP BA71_TP BB67_TP BB70_TP C1_TP CPU_A16_TP CPU_D4_TP CPU_D5_TP E71_TP RSVD_F65 RSVD_G65 RSVD_TP_AW70 RSVD_TP_AW71 RSVD_TP_BA68 RSVD_TP_BA70 RSVD_TP_BB68 RSVD_TP_BB69 TP1_AY4 TP2_BB3 TP4_BB5 TP5_AU5 TP6_AT5
net group THERM_SHUTDOWN: nets ALERT# PURE_HW_SHUTDOWN# T_CRIT# THERM_SYS_SHDN#
net group UART_MW-MW: nets UART0_CTS# UART0_RTS# UART1_CTS# UART1_RTS# UART_2_CRXD_DTXD UART_2_CRXD_DTXD_CON UART_2_CTXD_DRXD UART_2_CTXD_DRXD_CON
net group XDP-MW: nets XDP_PRDY# XDP_PREQ# XDP_TDI XDP_TDO_CPU XDP_TMS XDP_TRST#
net group XDP_BPM-MW: nets XDP_BPM0 XDP_BPM1 XDP_BPM2 XDP_BPM3
nets with their own width: min track width 0.508; nets GND

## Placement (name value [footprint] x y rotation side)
AFTP225  AFTE14P-GP  [AFTE14P-75]  71.91 12.74 0 top
AFTP2601  AFTE14P-GP  [AFTE14P-75]  152.7 75.91 0 top
AFTP2602  AFTE14P-GP  [AFTE14P-75]  150.8 75.53 0 top
AFTP2603  AFTE14P-GP  [AFTE14P-75]  151.56 77.44 0 top
AFTP2604  AFTE14P-GP  [AFTE14P-75]  153.47 78.07 0 top
AFTP2901  AFTE14P-GP  [AFTE14P-75]  16.81 6.44 90 top
AFTP2902  AFTE14P-GP  [AFTE14P-75]  16.33 8.3 90 top
AFTP2903  AFTE14P-GP  [AFTE14P-75]  16.05 4.61 0 top
AFTP2904  AFTE14P-GP  [AFTE14P-75]  13.87 1.77 0 top
AFTP4301  AFTE14P-GP  [AFTE14P-75]  19.61 82.26 0 top
AFTP4302  AFTE14P-GP  [AFTE14P-75]  19.18 84.17 0 top
AFTP4303  AFTE14P-GP  [AFTE14P-75]  24.66 86.73 0 top
AFTP4304  AFTE14P-GP  [AFTE14P-75]  19.58 76.98 0 top
AFTP4305  AFTE14P-GP  [AFTE14P-75]  21.92 86.58 0 top
AFTP4306  AFTE14P-GP  [AFTE14P-75]  171.75 27.91 0 top
AFTP4307  AFTE14P-GP  [AFTE14P-75]  171.58 25.92 0 top
AFTP4308  AFTE14P-GP  [AFTE14P-75]  169.42 27.14 0 top
AFTP4309  AFTE14P-GP  [AFTE14P-75]  166.67 24.1 0 top
AFTP4310  AFTE14P-GP  [AFTE14P-75]  164.77 24.1 0 top
AFTP4311  AFTE14P-GP  [AFTE14P-75]  161.92 23.99 0 top
AFTP4312  AFTE14P-GP  [AFTE14P-75]  158.42 31.21 0 top
AFTP4313  AFTE14P-GP  [AFTE14P-75]  156.51 31.21 0 top
AFTP4314  AFTE14P-GP  [AFTE14P-75]  157.45 29.51 0 top
AFTP4315  AFTE14P-GP  [AFTE14P-75]  168.58 24.1 0 top
AFTP6302  AFTE14P-GP  [AFTE14P-75]  202.03 17.16 0 top
AFTP6303  AFTE14P-GP  [AFTE14P-75]  194.36 14.55 0 top
AFTP6304  AFTE14P-GP  [AFTE14P-75]  201.32 22.55 0 top
AFTP6501  AFTE14P-GP  [AFTE14P-75]  76.5 9.24 0 top
AFTP6502  AFTE14P-GP  [AFTE14P-75]  72.57 9.36 0 top
AFTP6503  AFTE14P-GP  [AFTE14P-75]  71.55 7.59 0 top
AFTP6504  AFTE14P-GP  [AFTE14P-75]  92 8.55 0 top
AFTP6505  AFTE14P-GP  [AFTE14P-75]  74.47 9.36 0 top
AFTP6506  AFTE14P-GP  [AFTE14P-75]  75.36 7.59 0 top
AFTP6507  AFTE14P-GP  [AFTE14P-75]  86.03 9.19 0 top
AFTP6508  AFTE14P-GP  [AFTE14P-75]  73.46 7.59 0 top
AFTP6509  AFTE14P-GP  [AFTE14P-75]  77.27 7.46 0 top
AFTP6510  AFTE14P-GP  [AFTE14P-75]  79.17 7.46 0 top
AFTP6511  AFTE14P-GP  [AFTE14P-75]  84.12 9.24 0 top
AFTP6512  AFTE14P-GP  [AFTE14P-75]  78.41 9.11 0 top
AFTP6513  AFTE14P-GP  [AFTE14P-75]  86.92 7.41 0 top
AFTP6514  AFTE14P-GP  [AFTE14P-75]  80.31 9.24 0 top
AFTP6515  AFTE14P-GP  [AFTE14P-75]  81.08 7.46 0 top
AFTP6516  AFTE14P-GP  [AFTE14P-75]  83.06 7.43 0 top
AFTP6517  AFTE14P-GP  [AFTE14P-75]  82.22 9.19 0 top
AFTP6518  AFTE14P-GP  [AFTE14P-75]  85.01 7.38 0 top
AFTP6519  AFTE14P-GP  [AFTE14P-75]  89.08 6.77 0 top
AFTP6520  AFTE14P-GP  [AFTE14P-75]  90.09 8.55 0 top
AFTP6521  AFTE14P-GP  [AFTE14P-75]  92.89 6.77 0 top
AFTP6522  AFTE14P-GP  [AFTE14P-75]  94.79 6.77 0 top
AFTP6523  AFTE14P-GP  [AFTE14P-75]  93.9 8.55 0 top
AFTP6524  AFTE14P-GP  [AFTE14P-75]  90.98 6.77 0 top
AFTP6529  AFTE14P-GP  [AFTE14P-75]  105.46 4.66 0 top
AFTP6530  AFTE14P-GP  [AFTE14P-75]  105.41 7.03 0 top
AFTP6531  AFTE14P-GP  [AFTE14P-75]  130.61 8.09 0 top
AFTP6532  AFTE14P-GP  [AFTE14P-75]  124.64 6.7 0 top
AFTP6533  AFTE14P-GP  [AFTE14P-75]  125.02 8.6 0 top
AFTP6534  AFTE14P-GP  [AFTE14P-75]  128.42 7.66 0 top
AFTP6535  AFTE14P-GP  [AFTE14P-75]  129.84 6.32 0 top
AFTP6536  AFTE14P-GP  [AFTE14P-75]  126.92 9.24 0 top
AFTP6537  AFTE14P-GP  [AFTE14P-75]  126.54 7.33 0 top
AFTP6538  AFTE14P-GP  [AFTE14P-75]  91.24 10.38 0 top
AFTP6539  AFTE14P-GP  [AFTE14P-75]  88.19 8.83 0 top
BATT1  ETY-CON10-28-GP-U  [50299-01001-002-U]  164.7 21.71 180 bottom
C715  SC10U6D3V3MX-GP  [C603H38]  110.26 59.02 0 top
C716  SC1U10V2KX-1GP  [C402H22]  123.92 46.78 180 top
C717  SC1U10V2KX-1GP  [C402H22]  123.92 41.39 0 top
C718  SCD1U16V2KX-3DLGP  [C402H22]  77.4 60.76 0 top
C719  SC1U10V2KX-1GP  [C402H22]  76.51 60.76 0 top
C720  SCD1U16V2KX-3DLGP  [C402H22]  120.7 48.78 180 top
C721  SCD1U16V2KX-3DLGP  [C402H22]  120.7 47.31 0 top
C1101  SC1U10V2KX-1GP  [C402H22]  110.31 57.4 270 top
C1102  SC1U10V2KX-1GP  [C402H22]  109.68 73.58 270 top
C1103  SC1U10V2KX-1GP  [C402H22]  113.97 66.13 270 top
C1104  SC1U10V2KX-1GP  [C402H22]  117.65 66.01 270 top
C1105  SC1U10V2KX-1GP  [C402H22]  115.87 66.13 90 top
C1106  SC1U10V2KX-1GP  [C402H22]  108.79 77.56 270 top
C1107  SC1U10V2KX-1GP  [C402H22]  119.63 75.05 90 top
C1108  SC1U10V2KX-1GP  [C402H22]  110.41 51.43 270 top
C1109  SC1U10V2KX-1GP  [C402H22]  112.44 53.05 180 top
C1110  SC1U10V2KX-1GP  [C402H22]  110.39 54.22 270 top
C1111  SC1U10V2KX-1GP  [C402H22]  110.41 52.19 270 top
C1112  SC22U6D3V3MX-1-GP  [C603H40]  118.49 36.16 270 top
C1113  SC22U6D3V3MX-1-GP  [C603H40]  110.82 45.41 270 top
C1114  SC1U10V2KX-1GP  [C402H22]  120.11 44.31 180 top
C1115  SC22U6D3V3MX-1-GP  [C603H40]  119.23 46.35 180 top
C1116  SC1U10V2KX-1GP  [C402H22]  113.64 46.6 90 top
C1117  SC1U10V2KX-1GP  [C402H22]  113.69 47.46 90 top
C1118  SC22U6D3V3MX-1-GP  [C603H40]  117.4 47.18 90 top
C1119  SC1U10V2KX-1GP  [C402H22]  115.47 47.24 270 top
C1120  SC10U6D3V3MX-GP  [C603H38]  116.94 45.91 270 top
C1121  SC1U10V2KX-1GP  [C402H22]  116.08 48.23 270 top
C1122  SC22U6D3V3MX-1-GP  [C603H40]  113.56 36.95 0 top
C1123  SC10U6D3V3MX-GP  [C603H38]  110.89 46.91 270 top
C1124  SC1U10V2KX-1GP  [C402H22]  120.7 54.45 180 top
C1125  SC1U10V2KX-1GP  [C402H22]  109.65 56.23 270 top
C1126  SC1U10V2KX-1GP  [C402H22]  121.46 62.73 180 top
C1127  SC1U10V2KX-1GP  [C402H22]  121.59 59.63 180 top
C1202  SC10U6D3V3MX-GP  [C603H38]  63.85 64.76 180 top
C1203  SC10U6D3V3MX-GP  [C603H38]  64.9 60.85 180 top
C1204  SC10U6D3V3MX-GP  [C603H38]  64.43 56.2 270 top
C1205  SC10U6D3V3MX-GP  [C603H38]  72.86 54.24 180 top
C1206  SC10U6D3V3MX-GP  [C603H38]  72.21 60.93 180 top
C1207  SC1U10V2KX-1DLGP  [C402H22]  73.73 21.91 90 top
C1208  SC10U6D3V3MX-GP  [C603H38]  73.46 51.65 90 top
C1209  SC10U6D3V3MX-GP  [C603H38]  71.93 41.72 0 top
C1210  SC10U6D3V3MX-GP  [C603H38]  72.24 69.46 270 top
C1211  SC1U10V2KX-1DLGP  [C402H22]  70.86 24.27 180 top
C1212  SC1U10V2KX-1DLGP  [C402H22]  71.75 24.27 180 top
C1213  SC1U10V2KX-1DLGP  [C402H22]  73.73 22.75 90 top
C1214  SC1U10V2KX-1GP  [C402H22]  72.29 79.8 270 top
C1215  SC1U10V2KX-1GP  [C402H22]  62.81 74.36 270 top
C1216  SC1U10V2KX-1GP  [C402H22]  64.11 84.78 90 top
C1217  SC1U10V2KX-1GP  [C402H22]  64.69 41.49 90 top
C1218  SC1U10V2KX-1GP  [C402H22]  66.27 31.59 180 top
C1219  SC1U10V2KX-1GP  [C402H22]  72.63 56.31 90 top
C1220  SC1U10V2KX-1GP  [C402H22]  72.08 36.57 270 top
C1221  SC1U10V2KX-1GP  [C402H22]  72.03 26.18 270 top
C1222  SCD022U16V2KX-3GP  [C402H22]  72.61 48.92 270 top
C1223  SC1U10V2KX-1DLGP  [C402H22]  64.95 21.68 180 top
C1224  SC1U10V2KX-1DLGP  [C402H22]  63.17 21.68 180 top
C1225  SC1U10V2KX-1GP  [C402H22]  64.44 19.9 90 top
C1226  SC1U10V2KX-1GP  [C402H22]  64.44 19.02 90 top
C1227  SC1U10V2KX-1DLGP  [C402H22]  64.06 21.68 180 top
C1228  SCD1U16V2KX-L-GP  [C402H22]  70.08 22.44 90 top
C1229  SCD1U16V2KX-3DLGP  [C402H22]  72.63 47.18 90 top
C1230  SC1U10V2KX-1DLGP  [C402H22]  51.87 22.06 180 top
C1231  SC1U10V2KX-1DLGP  [C402H22]  62.28 22.83 180 top
C1232  SC1U10V2KX-1DLGP  [C402H22]  73.76 23.71 90 top
C1301  SCD1U16V2KX-3DLGP  [C402H22]  50.85 42.26 270 top
C1303  SC10U6D3V3MX-GP  [C603H38]  59.54 61.81 180 top
C1304  SC10U6D3V3MX-GP  [C603H38]  58.98 42.31 270 top
C1305  SC10U6D3V3MX-GP  [C603H38]  58.98 43.65 270 top
C1306  SC10U6D3V3MX-GP  [C603H38]  59.08 55.01 90 top
C1307  SC10U6D3V3MX-GP  [C603H38]  59.05 56.35 90 top
C1308  SC10U6D3V3MX-GP  [C603H38]  50.95 47.18 270 top
C1309  SC10U6D3V3MX-GP  [C603H38]  51.03 54.02 270 top
C1310  SC10U6D3V3MX-GP  [C603H38]  51 58.56 270 top
C1311  SC1U10V2KX-1DLGP  [C402H22]  61.39 22.83 180 top
C1312  SC1U10V2KX-1DLGP  [C402H22]  60.5 22.83 180 top
C1313  SC1U10V2KX-1DLGP  [C402H22]  58.7 22.06 180 top
C1314  SC1U10V2KX-1DLGP  [C402H22]  57.81 22.06 180 top
C1315  SC1U10V2KX-1GP  [C402H22]  51.51 64.56 180 top
C1316  SC1U10V2KX-1GP  [C402H22]  51.71 30.57 0 top
C1317  SC1U10V2KX-1GP  [C402H22]  54.18 27.27 90 top
C1318  SC1U10V2KX-1GP  [C402H22]  58.72 36.54 270 top
C1319  SC1U10V2KX-1GP  [C402H22]  51.48 74.03 0 top
C1320  SC1U10V2KX-1GP  [C402H22]  59.43 71.31 90 top
C1321  SC1U10V2KX-1GP  [C402H22]  58.8 80.03 270 top
C1322  SC1U10V2KX-1GP  [C402H22]  50.98 84.93 90 top
C1323  SCD022U16V2KX-3GP  [C402H22]  50.6 44.16 90 top
C1324  SC10U6D3V3MX-GP  [C603H38]  48.69 21.56 180 top
C1325  SC10U6D3V3MX-GP  [C603H38]  47.29 21.56 180 top
C1326  SC1U10V2KX-1GP  [C402H22]  50.98 22.06 180 top
C1327  SC1U10V2KX-1GP  [C402H22]  49.96 22.06 180 top
C1328  SCD1U16V2KX-L-GP  [C402H22]  56.54 22.52 90 top
C1329  SC2D2U10V3KX-L-GP  [C603H36]  50.93 25.44 270 top
C1330  SC1U10V2KX-1DLGP  [C402H22]  59.61 22.83 180 top
C1331  SC1U10V2KX-1DLGP  [C402H22]  72.54 24.27 180 top
C1601  SCD1U16V2KX-3DLGP  [C402H22]  133.27 47.46 90 bottom
C1602  SCD1U16V2KX-3DLGP  [C402H22]  133.27 46.7 90 bottom
C1605  SCD22U10V2KX-1GP  [C402H22]  130.94 42.82 90 bottom
C1606  SCD22U10V2KX-1GP  [C402H22]  130.94 41.93 90 bottom
C1607  SCD22U10V2KX-1GP  [C402H22]  130.94 40.15 90 bottom
C1608  SCD22U10V2KX-1GP  [C402H22]  130.94 41.04 90 bottom
C1609  SCD22U10V2KX-1GP  [C402H22]  130.99 43.73 90 bottom
C1610  SCD22U10V2KX-1GP  [C402H22]  130.99 44.62 90 bottom
C1611  SCD22U10V2KX-1GP  [C402H22]  130.99 46.19 90 bottom
C1612  SCD22U10V2KX-1GP  [C402H22]  130.99 45.43 90 bottom
C1701  SC220P50V2KX-3GP  [C402H22]  113.79 22.95 270 bottom
C1704  SC10U6D3V3MX-GP  [C603H38]  97.07 18.12 0 bottom
C1710  SCD47U10V2KX-GP  [C402H22]  149.02 16.22 180 top
C1711  SCD01U50V2KX-1GP  [C402H22]  105.08 93.82 0 bottom
C1801  SC15P50V2JN-2-GP  [C402H22]  131.93 52.29 180 bottom
C1802  SC15P50V2JN-2-GP  [C402H22]  131.49 49.22 270 bottom
C1803  SC9P50V2DN-GP  [C402H24]  100.38 21.71 180 bottom
C1804  SC9P50V2DN-GP  [C402H24]  100.38 23.41 0 bottom
C1805  SC1U10V2KX-1GP  [C402H22]  72.95 17.49 270 top
C1806  SC1U10V2KX-1GP  [C402H22]  74.78 14.72 90 top
C2101  SC1U10V2KX-1GP  [C402H22]  120.93 45.13 0 top
C2102  SC1U10V2KX-1GP  [C402H22]  95.68 20.41 90 top
C2103  SC1U10V2KX-1GP  [C402H22]  109.93 36.21 180 top
C2104  SC1U10V2KX-1GP  [C402H22]  109.98 49.42 180 top
C2105  SC1U10V2KX-1GP  [C402H22]  112.39 45.3 180 top
C2106  SC1U10V2KX-1GP  [C402H22]  112.49 47.01 0 top
C2107  SC1U10V2KX-1GP  [C402H22]  113.09 44.01 90 top
C2108  SC1U10V2KX-1GP  [C402H22]  114.6 36.75 0 top
C2109  SC1U10V2KX-1GP  [C402H22]  116.89 44.87 270 top
C2110  SCD1U16V2KX-3DLGP  [C402H22]  114.07 45.3 180 top
C2111  SCD1U16V2KX-3DLGP  [C402H22]  113.23 45.3 180 top
C2112  SCD1U16V2KX-3DLGP  [C402H22]  91.57 38.19 270 top
C2113  SC22U6D3V3MX-1-GP  [C603H40]  121.36 37.25 90 top
C2114  SC22U6D3V3MX-1-GP  [C603H40]  115.09 45.66 180 top
C2115  SC22U6D3V3MX-1-GP  [C603H40]  137.46 39.72 180 bottom
C2116  SC1U10V2KX-1GP  [C402H22]  110.41 50.66 270 top
C2117  SC1U10V2KX-1GP  [C402H22]  109.75 47.92 90 top
C2118  SCD1U16V2KX-3DLGP  [C402H22]  112.11 49.7 90 top
C2119  SC22U6D3V3MX-1-GP  [C603H40]  136.83 44.54 0 bottom
C2120  SC1U10V2KX-1GP  [C402H22]  95.68 19.65 90 top
C2121  SC1U10V2KX-1GP  [C402H22]  113.89 48.3 270 top
C2122  SC22U6D3V3MX-1-GP  [C603H40]  137.46 42.13 180 bottom
C2201  SC15P50V2JN-2-GP  [C402H22]  132.76 37.68 180 bottom
C2202  SC15P50V2JN-2-GP  [C402H22]  132.76 35.55 0 bottom
C2405  SC100P50V2JN-3GP  [C402H22]  178.79 32.71 270 top
C2406  SCD1U16V2KX-3DLGP  [C402H22]  178.71 31.56 180 top
C2407  SCD1U16V2KX-3DLGP  [C402H22]  186.59 31.46 0 bottom
C2408  SCD1U16V2KX-3DLGP  [C402H22]  190.14 32.83 0 bottom
C2409  SCD01U50V2KX-1GP  [C402H22]  195.45 43.78 270 bottom
C2410  SCD1U16V2KX-3DLGP  [C402H22]  198.3 37.86 270 bottom
C2411  SCD1U16V2KX-3DLGP  [C402H22]  186.33 44.34 270 bottom
C2412  SCD1U16V2KX-3DLGP  [C402H22]  192.07 41.37 90 bottom
C2413  SCD1U16V2KX-3DLGP  [C402H22]  194.11 34.89 0 bottom
C2414  SCD1U16V2KX-3DLGP  [C402H22]  185.09 36.11 180 bottom
C2415  SCD1U16V2KX-3DLGP  [C402H22]  186.49 10.38 180 bottom
C2416  SCD1U16V2KX-3DLGP  [C402H22]  202.23 29.33 0 top
C2418  SC1U10V2KX-1GP  [C402H22]  198.96 36.59 0 bottom
C2420  SCD1U16V2KX-3DLGP  [C402H22]  186.49 27.91 0 bottom
C2421  SCD1U16V2KX-3DLGP  [C402H22]  201.45 29.33 0 top
C2422  SCD1U16V2KX-3DLGP  [C402H22]  191.82 29.18 90 bottom
C2423  SCD1U16V2KX-3DLGP  [C402H22]  187.81 44.34 90 bottom
C2424  SC18P50V2JN-1DLGP  [C402H22]  199.69 26.51 0 top
C2425  SC18P50V2JN-1DLGP  [C402H22]  199.69 24.73 180 top
C2426  SC2D2U10V3KX-1DLGP-U  [C603H36]  187.65 28.85 180 bottom
C2428  SCD1U16V2KX-3DLGP  [C402H22]  191.95 31.33 90 bottom
C2429  SCD1U16V2KX-3DLGP  [C402H22]  198.3 38.62 270 bottom
C2435  SC2200P50V2KX-2GP  [C402H22]  188.31 31.21 0 bottom
C2436  SC2200P50V2KX-2GP  [C402H22]  197.84 39.95 0 bottom
C2441  SC2200P50V2KX-2GP  [C402H22]  190.55 27.91 0 bottom
C2501  SC10U10V5KX-2GP  [C805H54]  121.72 12.16 180 bottom
C2502  SCD1U16V2KX-3GP  [C402H22]  123.11 12.41 180 bottom
C2503  SCD47U25V3KX-1-DL-GP  [C603H36]  143.71 17.54 0 bottom
C2601  SC10U6D3V3MX-GP  [C603H38]  141.5 26.76 0 bottom
C2602  SCD1U16V2KX-3DLGP  [C402H22]  136.83 27.86 270 bottom
C2603  SC2200P50V2KX-2GP  [C402H22]  152.96 75.53 180 bottom
C2604  SC4D7U6D3V3KX-GP  [C603H36]  151.81 75.53 180 bottom
C2605  SCD1U16V2KX-3DLGP  [C402H22]  153.85 75.53 180 bottom
C2606  SC470P50V3JN-2GP  [C603H36]  46.07 94.66 90 bottom
C2607  SC2200P50V2KX-2GP  [C402H22]  46.86 96.13 0 bottom
C2608  SCD1U16V2KX-3GP  [C402H22]  136.6 23.33 0 top
C2609  SCD1U16V2KX-3GP  [C402H22]  135.79 23.33 0 top
C2610  SCD1U16V2KX-3GP  [C402H22]  144.8 24.63 0 bottom
C2612  SCD1U16V2KX-3DLGP  [C402H22]  123.9 32.71 180 bottom
C2613  SC100P50V2JN-3GP  [C402H22]  195.93 41.47 90 bottom
C2701  SCD1U16V2KX-3DLGP  [C402H22]  23.85 19.45 180 bottom
C2702  SC10U6D3V3MX-GP  [C603H38]  17.52 13.02 270 bottom
C2703  SC1U50V3KX-GP  [C603H32]  21.35 22.11 90 bottom
C2704  SC1U50V3KX-GP  [C603H32]  20.83 19.75 0 bottom
C2705  SC2D2U10V3KX-1GP  [C603H36]  18.31 14.29 270 bottom
C2706  SC10U6D3V3MX-GP  [C603H38]  22.86 14.85 0 bottom
C2707  SCD1U16V2KX-3DLGP  [C402H22]  21.84 14.65 0 bottom
C2708  SC10U6D3V3MX-GP  [C603H38]  25.83 15.21 90 bottom
C2709  SCD1U16V2KX-3DLGP  [C402H22]  24.18 14.7 0 bottom
C2710  SCD1U16V2KX-3DLGP  [C402H22]  22.38 11.4 180 bottom
C2711  SC4D7U6D3V3KX-GP  [C603H36]  23.39 11.4 180 bottom
C2712  SC10U6D3V3MX-GP  [C603H38]  23.72 22.11 270 bottom
C2713  SC10U6D3V3MX-GP  [C603H38]  19 18.58 90 bottom
C2714  SC1U10V2KX-1GP  [C402H22]  18.9 27.6 90 bottom
C2715  SC4D7U6D3V3KX-GP  [C603H36]  22.66 23.38 90 bottom
C2716  SC4D7U6D3V3KX-GP  [C603H36]  29.59 24.17 90 top
C2717  SCD1U16V2KX-3DLGP  [C402H22]  26.34 16.35 90 bottom
C2718  SC10U6D3V3MX-GP  [C603H38]  27.81 22.34 180 top
C2719  SCD1U16V2KX-3DLGP  [C402H22]  29.31 20.9 90 top
C2720  SCD1U16V2KX-3DLGP  [C402H22]  26.92 10.91 90 bottom
C2721  SCD1U16V2KX-3GP  [C402H22]  24.03 26.36 0 bottom
C2722  SCD1U16V2KX-3DLGP  [C402H22]  18.92 26.76 90 bottom
C2723  SC33P50V2JN-3GP  [C402H22]  32.33 16.02 180 top
C2724  SC4D7U6D3V3KX-GP  [C603H36]  22.78 19.57 180 bottom
C2902  SC10U6D3V3MX-GP  [C603H38]  19.53 20.41 180 bottom
C2907  SC10U6D3V3MX-GP  [C603H38]  17.32 15.56 90 bottom
C2908  SC10U6D3V3MX-GP  [C603H38]  18.99 22.24 90 bottom
C3401  SC1U10V2KX-1GP  [C402H22]  18.82 56.76 0 bottom
C3402  SCD1U16V2KX-3DLGP  [C402H22]  23.29 42 180 bottom
C3403  SCD1U16V2KX-3DLGP  [C402H22]  19.63 56.76 0 bottom
C3404  SC22U6D3V3MX-1-GP  [C603H40]  23.09 57.12 270 bottom
C3405  SC22U6D3V3MX-1-GP  [C603H40]  23.09 55.85 270 bottom
C3406  SC10U6D3V3MX-DL-GP  [C603H36]  24.31 42.33 180 bottom
C3407  SC1KP50V2KX-1DLGP  [C402H22]  18.06 56.76 0 bottom
C3502  SCD1U16V2KX-3DLGP  [C402H22]  24.56 35.4 180 bottom
C3503  SCD1U16V2KX-3GP  [C402H22]  23.67 35.4 180 bottom
C3507  SCD1U16V2KX-3DLGP  [C402H22]  18.59 38.32 0 bottom
C3508  SC1U10V2KX-1GP  [C402H22]  18.46 35.02 180 bottom
C3512  SC22U6D3V5MX-2GP  [C805H58]  21.26 35.02 180 bottom
C3513  SC10U6D3V3MX-GP  [C603H38]  19.61 38.45 0 bottom
C3514  SC10U6D3V3MX-GP  [C603H38]  19.61 35.02 180 bottom
C3601  SCD1U16V2KX-3DLGP  [C402H22]  24.69 53.31 270 top
C3602  SCD1U16V2KX-3DLGP  [C402H22]  24.69 54.07 270 top
C3603  SCD1U16V2KX-3DLGP  [C402H22]  24.56 31.59 270 top
C3604  SCD1U16V2KX-3DLGP  [C402H22]  24.56 32.48 270 top
C3701  SCD1U16V2KX-3GP  [C402H22]  32.15 49.34 270 top
C3702  SCD1U16V2KX-3GP  [C402H22]  32.15 48.51 270 top
C3703  SC1U10V2KX-1GP  [C402H22]  32.15 47.57 270 top
C3704  SC1U10V2KX-1GP  [C402H22]  23.95 35.09 0 top
C3705  SCD1U16V2KX-3GP  [C402H22]  24.79 35.09 0 top
C3707  SC1U50V3KX-GP  [C603H32]  24.2 92.42 0 top
C3709  SCD1U16V2KX-3GP  [C402H22]  30.71 93.49 180 top
C3710  SC2D2U10V3KX-1GP  [C603H36]  32.33 92.73 90 top
C3711  SC390P50V2KX-GP-U  [C402H24]  21 40.99 0 top
C3712  SC390P50V2KX-GP-U  [C402H24]  21 42.76 180 top
C3715  SC1U10V2KX-1GP  [C402H22]  28.37 47.46 180 top
C3716  SCD1U16V2KX-3GP  [C402H22]  27.35 33.37 0 top
C3717  SCD1U16V2KX-3GP  [C402H22]  31.01 32.63 270 top
C3718  SC10U6D3V3MX-GP  [C603H38]  22.88 35.32 0 top
C3719  SCD1U16V2KX-3GP  [C402H22]  25.63 35.07 0 top
C3720  SCD22U10V2KX-1GP  [C402H22]  20.75 96.61 90 top
C3721  SCD1U16V2KX-3DLGP  [C402H22]  29.77 48.61 90 top
C3722  SC1U10V2KX-1GP  [C402H22]  29.77 49.37 90 top
C3723  SCD1U16V2KX-3DLGP  [C402H22]  29.77 47.84 90 top
C3801  SCD1U16V2KX-3GP  [C402H22]  35.66 65.12 270 top
C3802  SCD1U16V2KX-3GP  [C402H22]  35.66 65.88 270 top
C3803  SCD1U16V2KX-3GP  [C402H22]  32.43 51.53 90 top
C3804  SCD1U16V2KX-3GP  [C402H22]  32.43 52.42 90 top
C3805  SCD1U16V2KX-3GP  [C402H22]  31.93 53.31 90 top
C3806  SCD1U16V2KX-3GP  [C402H22]  31.93 54.19 90 top
C3807  SCD1U16V2KX-3GP  [C402H22]  41.07 57.37 270 top
C3808  SCD1U16V2KX-3GP  [C402H22]  41.07 60.04 270 top
C3809  SCD1U16V2KX-3GP  [C402H22]  41.07 59.15 270 top
C3810  SCD1U16V2KX-3GP  [C402H22]  41.07 61.81 270 top
C3811  SCD1U16V2KX-3GP  [C402H22]  41.07 60.93 270 top
C3812  SCD1U16V2KX-3GP  [C402H22]  41.1 54.4 270 top
C3813  SCD1U16V2KX-3GP  [C402H22]  41.1 55.16 270 top
C3814  SCD1U16V2KX-3GP  [C402H22]  41.07 56.48 270 top
C3815  SC1U10V2KX-1GP  [C402H22]  29.01 56.1 270 top
C3816  SC1U10V2KX-1GP  [C402H22]  29.01 62.58 270 top
C3817  SCD1U16V2KX-3GP  [C402H22]  38.02 62.83 90 top
C3818  SC1U10V2KX-1GP  [C402H22]  34.43 54.07 90 top
C3819  SC2D2U10V3KX-1DLGP-U  [C603H36]  26.72 61.05 180 top
C3820  SCD1U16V2KX-3GP  [C402H22]  27.74 61.56 180 top
C3821  SCD1U25V2KX-GP  [C402H22]  25.22 92.93 0 top
C3861  SCD1U16V2KX-3GP  [C402H22]  20.52 100.42 270 top
C3862  SCD1U16V2KX-3GP  [C402H22]  20.52 99.66 270 top
C3863  SCD1U16V2KX-3GP  [C402H22]  22.43 90.31 180 top
C3864  SCD1U16V2KX-3GP  [C402H22]  21.66 90.31 180 top
C3865  SCD1U16V2KX-3GP  [C402H22]  40.36 39.29 180 top
C4001  SC470P50V2KX-3GP  [C402H22]  138.12 102.33 270 bottom
C4002  SC470P50V2KX-3GP  [C402H22]  138.12 103.17 270 bottom
C4004  SC10U6D3V3MX-DL-GP  [C603H36]  138.1 104.46 270 bottom
C4005  SC10U6D3V3MX-DL-GP  [C603H36]  137.77 100.96 270 bottom
C4006  SC10U6D3V3MX-GP  [C603H38]  87.04 92.17 270 top
C4007  SCD1U16V2KX-3DLGP  [C402H22]  93.42 88.84 270 top
C4008  SCD1U16V2KX-3GP  [C402H22]  101.01 92.8 180 top
C4009  SC10U6D3V3MX-GP  [C603H38]  116.89 18.89 270 bottom
C4010  SCD22U10V2KX-1GP  [C402H22]  132.89 103.57 90 top
C4011  SCD22U10V2KX-1GP  [C402H22]  132.89 104.33 90 top
C4012  SC10U6D3V3MX-GP  [C603H38]  112.22 17.01 270 bottom
C4013  SC10U6D3V3MX-GP  [C603H38]  138.3 13.73 270 bottom
C4031  SC1U10V2KX-1GP  [C402H22]  105.48 16.68 180 bottom
C4032  SC1U10V2KX-1GP  [C402H22]  88.7 90.52 270 top
C4033  SC1U10V2KX-1GP  [C402H22]  90.47 88.61 0 top
C4034  SC1U10V2KX-1GP  [C402H22]  104.72 16.83 180 bottom
C5501  SCD1U16V2KX-3DLGP  [C402H22]  89.28 95.14 180 top
C5502  SC4D7U6D3V3KX-GP  [C603H36]  78.28 99.48 270 top
C5503  SC4D7U6D3V3KX-GP  [C603H36]  59.1 92.96 90 top
C5504  SCD1U16V2KX-3DLGP  [C402H22]  90.17 95.14 180 top
C5505  SC4D7U6D3V3KX-GP  [C603H36]  81.76 93.18 270 top
C5506  SCD1U16V2KX-3DLGP  [C402H22]  91.06 95.14 180 top
C5507  SCD1U16V2KX-3DLGP  [C402H22]  81.84 94.3 270 top
C5508  SC1U10V2KX-1GP  [C402H22]  81.84 95.14 90 top
C5509  SCD1U16V2KX-3DLGP  [C402H22]  91.95 95.14 180 top
C5510  SCD1U16V2KX-3DLGP  [C402H22]  83.95 95.14 180 top
C5511  SCD1U16V2KX-3DLGP  [C402H22]  84.83 95.14 180 top
C5512  SCD1U50V3KX-GP  [C603H36]  79.04 92.55 0 top
C5513  SC1KP50V2KX-1GP  [C402H22]  80.08 95.27 90 top
C5514  SC2D2U35V3KX-GP  [C603H40]  77.72 92.55 0 top
C5515  SC4D7U6D3V3KX-GP  [C603H36]  52.88 99.18 180 top
C5516  SCD1U50V3KX-GP  [C603H36]  68.25 92.93 90 top
C5517  SC4D7U6D3V3KX-GP  [C603H36]  68.25 94.83 90 top
C5518  SC2D2U35V3KX-GP  [C603H40]  76.43 92.55 0 top
C5519  SCD1U16V2KX-3DLGP  [C402H22]  88.39 95.14 180 top
C5520  SC10U6D3V3MX-GP  [C603H38]  68.25 96.1 90 top
C5531  SCD1U16V2KX-3DLGP  [C402H22]  86.61 95.14 180 top
C5532  SCD1U16V2KX-3DLGP  [C402H22]  85.72 95.14 180 top
C5533  SCD1U16V2KX-3DLGP  [C402H22]  87.5 95.14 180 top
C5534  SC1KP50V2KX-1GP  [C402H22]  54.43 90.47 270 top
C5542  SCD1U50V3KX-GP  [C603H36]  54.3 91.74 90 top
C5701  SC10U6D3V3MX-DL-GP  [C603H36]  26.59 71.09 0 top
C5702  SC10U6D3V3MX-DL-GP  [C603H36]  19.71 70.55 0 top
C5703  SCD1U16V2KX-3DLGP  [C402H22]  23.93 62.6 270 bottom
C5704  SCD1U16V2KX-3DLGP  [C402H22]  24.56 63.72 180 bottom
C5705  SC100P50V2JN-3DLGP  [C402H22]  20.72 70.22 0 top
C5706  SCD1U16V2KX-3DLGP  [C402H22]  21.49 70.22 0 top
C5707  SCD1U16V2KX-3DLGP  [C402H22]  29.77 66.89 270 top
C5708  SCD1U16V2KX-3DLGP  [C402H22]  29.77 63.97 270 top
C5709  SCD1U16V2KX-3DLGP  [C402H22]  27.86 67.15 270 top
C5710  SCD1U16V2KX-3DLGP  [C402H22]  29.77 66.13 270 top
C5711  SCD1U16V2KX-3DLGP  [C402H22]  29.77 64.74 270 top
C5712  SCD1U16V2KX-3DLGP  [C402H22]  27.86 65.75 270 top
C5713  SCD1U16V2KX-3DLGP  [C402H22]  19.58 59.81 180 top
C5714  SCD1U16V2KX-3DLGP  [C402H22]  27.86 67.91 270 top
C5715  SCD1U16V2KX-3DLGP  [C402H22]  27.86 64.99 270 top
C5716  SCD1U16V2KX-3DLGP  [C402H22]  21.51 63.97 90 bottom
C5717  SC100P50V2JN-3DLGP  [C402H22]  25.58 70.83 0 top
C6001  SCD01U50V2KX-1GP  [C402H22]  171.83 12.62 90 top
C6002  SCD1U16V2KX-3DLGP  [C402H22]  178.41 21.51 0 top
C6003  SCD01U50V2KX-1GP  [C402H22]  171.83 13.51 90 top
C6004  SC1U10V2KX-1DLGP  [C402H22]  179.17 21.51 180 top
C6005  SCD01U50V2KX-1GP  [C402H22]  171.83 15.29 90 top
C6006  SCD01U50V2KX-1GP  [C402H22]  171.83 14.4 90 top
C6007  SCD1U16V2KX-3GP  [C402H22]  177.09 16.22 0 top
C6008  SCD1U16V2KX-3GP  [C402H22]  171.78 18.28 270 top
C6009  SC1U10V2KX-1DLGP  [C402H22]  173.71 19.4 90 top
C6010  SCD1U16V2KX-3GP  [C402H22]  175.39 19.4 270 top
C6302  SCD22U10V2KX-1GP  [C402H22]  186.56 16.2 270 top
C6303  SCD22U10V2KX-1GP  [C402H22]  186.56 15.31 270 top
C6304  SC33P50V2JN-3GP  [C402H22]  202.18 21.15 90 top
C6305  SC33P50V2JN-3GP  [C402H22]  200.61 21.15 270 top
C6306  SCD047U25V2KX-GP  [C402H22]  202.23 13.3 90 top
C6307  SCD1U16V2KX-3GP  [C402H22]  202.21 20.31 90 top
C6308  SCD047U25V2KX-GP  [C402H22]  202.23 14.14 90 top
C6311  SCD22U10V2KX-1GP  [C402H22]  185.57 13.45 270 top
C6312  SCD22U10V2KX-1GP  [C402H22]  185.57 12.56 270 top
C6313  SCD22U10V2KX-1GP  [C402H22]  195.5 10.74 0 top
C6314  SCD22U10V2KX-1GP  [C402H22]  196.26 10.74 0 top
C6315  SCD22U10V2KX-1GP  [C402H22]  189.53 11.68 270 top
C6316  SCD22U10V2KX-1GP  [C402H22]  189.53 10.84 270 top
C6317  SC22U6D3V3MX-1-GP  [C603H40]  200.96 8.86 180 bottom
C6318  SC22U6D3V3MX-1-GP  [C603H40]  199.69 8.86 180 bottom
C6501  SCD1U16V2KX-3DLGP  [C402H22]  106.86 5.05 180 top
C6502  SCD1U16V2KX-3DLGP  [C402H22]  143.89 13.28 0 bottom
C6503  SCD1U16V2KX-3DLGP  [C402H22]  138.73 17.49 270 bottom
C6504  SCD1U16V2KX-3GP  [C402H22]  113.05 18.05 90 bottom
C7001  SCD047U16V2KX-1-GP  [C402H22]  17.14 83.4 180 top
C7002  SCD1U16V2KX-3DLGP  [C402H22]  16.66 84.67 90 top
C7003  SCD1U16V2KX-3DLGP  [C402H22]  174.9 43.2 90 top
C7004  SC10U6D3V3MX-GP  [C603H38]  176.3 45.46 0 top
C9101  SC2200P50V2KX-2GP  [C402H22]  42.98 22.7 0 top
C9102  SCD1U16V2KX-3DLGP  [C402H22]  44.75 22.7 0 top
C9104  SC2200P50V2KX-2GP  [C402H22]  43.86 22.7 0 top
C9105  SC4D7U6D3V3KX-GP  [C603H36]  45.9 22.57 0 top
C9106  SC4D7U6D3V3KX-GP  [C603H36]  33.37 32.6 180 top
C9113  SCD1U16V2KX-3GP  [C402H22]  34.47 30.8 0 top
C9114  SC4D7U6D3V3KX-GP  [C603H36]  32.31 25.49 0 top
CPU1  SKYLAKE-U-GP  [BGA1356M4224-U2H52]  114.6 56.71 270 bottom
D1701  RB751V-40H-GP  [SOD323AKH38]  150.9 30.45 90 bottom
D2402  RB751V-40H-GP  [SOD323AKH38]  186.49 38.02 270 bottom
D2403  RB751V-40H-GP  [SOD323AKH38]  186.79 40.07 90 bottom
D2501  BAS40C-2-GP  [SOT-23-9H44]  147.5 17.49 270 bottom
D2601  RB551V30-GP  [SOD323AKH38]  148.74 76.29 270 bottom
D2701  BAT54C-11-GP  [SOT23-2D4-312H44]  28.95 12.18 270 bottom
D3701  SBA0520Q-R1-00001-GP-U  [D1006-0305AK-UH22]  27.74 91.28 0 top
D3702  SBA0520Q-R1-00001-GP-U  [D1006-0305AK-UH22]  29.46 91.28 0 top
D4001  LBAS16LT1G-GP  [SOT23-2D4-312H44]  116.64 15.33 0 bottom
D4002  RB751V-40H-GP  [SOD323AKH38]  162.74 103.22 0 bottom
D4304  LBAV99LT1G-1-GP  [SOT23-2D4-312H44]  151.51 23.44 0 bottom
D4305  LBAV99LT1G-1-GP  [SOT23-2D4-312H44]  163.49 32.2 0 bottom
D4306  LBAV99LT1G-1-GP  [SOT23-2D4-312H44]  159.58 32.2 0 bottom
D5501  BAT54C-11-GP  [SOT23-2D4-312H44]  92.86 98.85 0 top
D5502  BAT54C-11-GP  [SOT23-2D4-312H44]  102.77 97.5 180 top
D5503  BAT54C-11-GP  [SOT23-2D4-312H44]  96.85 97.83 270 top
D5701  LBAW56LT1G-GP  [SOT23-2D4-312H44]  22.99 59.78 0 bottom
D7001  BAT54A-7-F-2-GP  [SOT23-2D4-312H48]  117.65 10.76 180 bottom
DB1  ACES-CON14-5-GP  [87212-1400N]  166.42 7.79 180 top
DB3  ACES-CON6-58-GP  [50696-00601-001]  158.67 16.6 270 top
DCIN1  ACES-CON8-13-GP-U2  [50224-0080N-W02-U]  19.55 89.71 0 bottom
DM1  DDR4-260P-65-GP  [ADDR0206-P013A]  67.95 54.11 270 bottom
DM2  DDR4-260P-64-GP  [ADDR0205-P012A]  55 54.31 90 bottom
EC1001  SCD1U25V2KX-L-GP  [C402H22]  112.57 50.89 0 top
EC1002  SCD1U25V2KX-L-GP  [C402H22]  143.69 68.8 180 top
EC1003  SCD1U25V2KX-L-GP  [C402H22]  144.07 62.83 0 top
EC1004  SCD1U25V2KX-L-GP  [C402H22]  123.16 63.57 270 top
EC1005  SC1U10V2KX-1GP  [C402H22]  111.81 77.18 90 top
EC1006  SCD1U25V2KX-L-GP  [C402H22]  114.35 76.04 270 top
EC1007  SCD1U25V2KX-L-GP  [C402H22]  114.6 50.64 0 top
EC1102  SC2D2U10V2KX-GP  [C402H22]  91.57 67 180 top
EC1103  SC2D2U10V2KX-GP  [C402H22]  59.69 85.56 180 top
EC1202  SC2D2U10V2KX-GP  [C402H22]  74.73 30.37 90 top
EC1302  SC2D2U10V2KX-GP  [C402H22]  51.2 90.87 90 top
EC1303  SC2D2U10V2KX-GP  [C402H22]  59.41 25.9 0 top
EC1706  SC1KP50V2KX-1GP  [C402H22]  118.72 44.72 90 top
EC1707  SCD1U16V2KX-3GP  [C402H22]  107.49 19.88 180 bottom
EC1710  SC2D2U10V2KX-GP  [C402H22]  87.43 93.18 270 top
EC1712  SCD1U16V2KX-3GP  [C402H22]  150.42 19.9 90 top
EC1713  SC2D2U10V2KX-GP  [C402H22]  55.6 15.21 180 bottom
EC1803  SC4D7P50V2BN-GP  [C402H22]  94.38 50.28 90 top
EC1804  SC10P50V2JN-4GP  [C402H22]  89.58 28.54 90 top
EC1806  SCD1U16V2KX-3GP  [C402H22]  72.95 18.25 270 top
EC1807  SCD1U16V2KX-3GP  [C402H22]  74.78 15.49 90 top
EC1901  SC10P50V2JN-4GP  [C402H22]  90.02 46.73 270 top
EC1902  SCD1U16V2KX-3GP  [C402H22]  93.65 45.99 270 top
EC2002  SC1KP50V2KX-1GP  [C402H22]  116.56 36.41 90 top
EC2101  SCD1U25V2KX-GP  [C402H22]  95.68 18.89 90 top
EC2501  SC4D7P50V2BN-GP  [C402H22]  122.86 18.46 270 bottom
EC2502  SC4D7P50V2BN-GP  [C402H22]  123.19 20.79 180 bottom
EC2503  SC10P50V2JN-4GP  [C402H22]  122.86 17.7 270 bottom
EC2504  SCD1U16V2KX-3GP  [C402H22]  140.79 10.84 0 top
EC2701  SC33P50V2JN-3GP  [C402H22]  30.43 15.64 90 top
EC2703  SCD1U25V2KX-GP  [C402H22]  15.04 11.22 0 top
EC2704  SC1KP50V2KX-1GP  [C402H22]  19.56 12.13 0 top
EC2705  SCD1U25V2KX-GP  [C402H22]  14.55 9.95 90 top
EC2706  SC1KP50V2KX-1GP  [C402H22]  18.06 10.38 180 bottom
EC2707  SC1KP50V2KX-1GP  [C402H22]  18.9 10.38 180 bottom
EC2708  SC33P50V2JN-3GP  [C402H22]  33.35 19.98 270 top
EC2709  SC33P50V2JN-3GP  [C402H22]  32.33 17.54 0 top
EC2901  SC100P50V2JN-3GP  [C402H22]  18.97 2.76 0 top
EC2902  SC100P50V2JN-3GP  [C402H22]  18.49 5.81 180 top
EC2903  SC100P50V2JN-3GP  [C402H22]  20.06 8.42 0 top
EC2904  SC100P50V2JN-3GP  [C402H22]  20.75 11.57 270 top
EC2905  SC100P50V2JN-3GP  [C402H22]  15.21 15.74 0 top
EC2906  SC100P50V2JN-3GP  [C402H22]  18.51 15.08 0 top
EC2907  SC100P50V2JN-3GP  [C402H22]  18.21 17.06 0 bottom
EC2908  SC100P50V2JN-3GP  [C402H22]  16.99 20.62 270 bottom
EC2909  SC1KP50V2KX-1DLGP  [C402H22]  18.59 7.08 90 top
EC2910  SC1KP50V2KX-1DLGP  [C402H22]  15.77 2.81 180 top
EC2911  SC1KP50V2KX-1DLGP  [C402H22]  16.23 9.64 270 top
EC2912  SC1KP50V2KX-1DLGP  [C402H22]  14.78 3.37 0 top
EC4301  SC10U25V3MX-GP  [C603H40]  18.54 81.75 90 bottom
EC4302  SCD1U25V2KX-GP  [C402H22]  18.62 82.85 90 bottom
EC4306  SC10P50V2JN-4GP  [C402H22]  165.86 26.18 180 top
EC4307  SCD1U25V2KX-GP  [C402H22]  153.72 27.78 90 bottom
EC4308  SCD1U50V3KX-GP  [C603H36]  159.92 29.1 270 bottom
EC4309  SC10P50V2JN-4GP  [C402H22]  162.74 27.37 270 top
EC4310  SC10P50V2JN-4GP  [C402H22]  164.46 27.37 90 top
EC4425  SC2D2U10V2KX-GP  [C402H22]  158.27 45.94 0 top
EC4534  SCD1U25V2KX-GP  [C402H22]  161.26 62.5 0 top
EC4701  SCD1U25V2KX-GP  [C402H22]  160.96 70.45 0 bottom
EC4801  SCD1U25V2KX-GP  [C402H22]  145.11 94.4 180 bottom
EC5001  SCD1U25V2KX-GP  [C402H22]  152.83 61.84 0 bottom
EC5501  SC6D8P50V2DN-GP  [C402H22]  99.49 92.8 180 top
EC5502  SCD1U25V2KX-GP  [C402H22]  58.72 94 90 top
EC5503  SC22P50V2JN-4GP  [C402H22]  58.09 90.39 180 top
EC5504  SC22P50V2JN-4GP  [C402H22]  59.23 89.37 0 top
EC5505  SC33P50V2JN-3GP  [C402H22]  53.97 99.1 180 top
EC6401  SC220P50V2KX-3GP  [C402H22]  67.31 12.59 0 bottom
EC6402  SC220P50V2KX-3GP  [C402H22]  53.26 5.55 270 bottom
EC6501  SC33P50V2JN-3GP  [C402H22]  127.18 3.75 180 top
EC6502  SC33P50V2JN-3GP  [C402H22]  122.99 3.9 180 top
EC6503  SC33P50V2JN-3GP  [C402H22]  134.54 22.95 90 top
EC6504  SC33P50V2JN-3GP  [C402H22]  132.89 21.81 270 top
EC6505  SC100P50V2JN-3GP  [C402H22]  71.55 4.03 0 top
EC6506  SC100P50V2JN-3GP  [C402H22]  70.66 4.03 0 top
EC6507  SC100P50V2JN-3GP  [C402H22]  69.77 4.03 0 top
EC6508  SC100P50V2JN-3GP  [C402H22]  68.88 4.03 0 top
EC6509  SC100P50V2JN-3GP  [C402H22]  67.99 4.03 0 top
EC6510  SC100P50V2JN-3GP  [C402H22]  67.11 4.03 0 top
EC6511  SC100P50V2JN-3GP  [C402H22]  66.22 4.03 0 top
EC6512  SC100P50V2JN-3GP  [C402H22]  65.33 4.03 0 top
EC6513  SC100P50V2JN-3GP  [C402H22]  92.38 3.9 0 top
EC6514  SC100P50V2JN-3GP  [C402H22]  95.93 3.9 0 top
EC6515  SC100P50V2JN-3GP  [C402H22]  97.71 3.9 0 top
EC6516  SC100P50V2JN-3GP  [C402H22]  98.6 3.9 0 top
EC6517  SC100P50V2JN-3GP  [C402H22]  95.05 3.9 0 top
EC6518  SC100P50V2JN-3GP  [C402H22]  96.82 3.9 0 top
EC6519  SC100P50V2JN-3GP  [C402H22]  94.16 3.9 0 top
EC6520  SC100P50V2JN-3GP  [C402H22]  93.27 3.9 0 top
EC6521  SC100P50V2JN-3GP  [C402H22]  73.2 4.03 0 top
EC6522  SC100P50V2JN-3GP  [C402H22]  88.82 3.9 0 top
EC6523  SC100P50V2JN-3GP  [C402H22]  90.6 3.9 0 top
EC6524  SC100P50V2JN-3GP  [C402H22]  91.49 3.9 0 top
EC6525  SC100P50V2JN-3GP  [C402H22]  87.93 3.9 0 top
EC6526  SC100P50V2JN-3GP  [C402H22]  89.71 3.9 0 top
EC6527  SC100P50V2JN-3GP  [C402H22]  87.04 3.9 0 top
EC6528  SC100P50V2JN-3GP  [C402H22]  74.09 4.03 0 top
EC6529  SC100P50V2JN-3GP  [C402H22]  72.44 4.03 0 top
EC6530  SC100P50V2JN-3GP  [C402H22]  94.11 10.15 90 top
EC6601  SC33P50V2JN-3GP  [C402H22]  168.53 35.6 90 top
EC6602  SC33P50V2JN-3GP  [C402H22]  168.35 45.36 180 top
EC6603  SC33P50V2JN-3GP  [C402H22]  165.02 44.8 0 bottom
EC8901  SCD1U25V2KX-GP  [C402H22]  23.34 24.76 180 top
EC8902  SC1KP50V2KX-1GP  [C402H22]  19.3 24.78 0 bottom
EC8903  SCD1U25V2KX-GP  [C402H22]  21.99 24.76 180 top
EC8904  SC1KP50V2KX-1GP  [C402H22]  21.13 24.76 180 top
EC8905  SC1U50V3KX-GP  [C603H32]  52.42 92.47 0 top
EC8906  SC2200P50V2KX-2GP  [C402H22]  175.39 58.59 180 top
EC8907  SCD1U25V2KX-GP  [C402H22]  53.14 3.52 90 top
EC8908  SCD1U25V2KX-GP  [C402H22]  139.37 51.27 270 top
EC8909  SCD1U25V2KX-GP  [C402H22]  56.69 24.98 90 top
EC8910  SCD1U25V2KX-GP  [C402H22]  44.12 40.73 270 top
EC8911  SCD1U25V2KX-GP  [C402H22]  43.86 45.94 90 top
EC8912  SCD1U25V2KX-GP  [C402H22]  145.08 12.79 270 bottom
EC8913  SCD1U25V2KX-GP  [C402H22]  25.14 76.57 0 top
EC8914  SCD1U25V2KX-GP  [C402H22]  34.97 13.43 180 top
EC8915  SCD1U25V2KX-GP  [C402H22]  120.11 107.36 180 top
EC8916  SCD1U25V2KX-GP  [C402H22]  134.92 105.12 270 top
EC8917  SCD1U25V2KX-GP  [C402H22]  70.66 98.9 0 top
EC8918  SC1KP50V2KX-1GP  [C402H22]  76.66 66.85 180 top
EC8919  SCD1U25V2KX-GP  [C402H22]  77.6 66.83 180 top
EC8920  SCD1U25V2KX-GP  [C402H22]  78.36 60.8 0 top
EC8921  SCD1U25V2KX-GP  [C402H22]  79.25 60.8 0 top
EC8922  SCD1U25V2KX-GP  [C402H22]  80.27 60.8 0 top
EC8923  SCD1U25V2KX-GP  [C402H22]  78.49 66.83 180 top
EC8924  SCD1U25V2KX-GP  [C402H22]  79.38 66.83 180 top
EC8925  SCD1U25V2KX-GP  [C402H22]  83.14 66.83 180 top
EC8926  SC2D2U10V2KX-GP  [C402H22]  170.23 94.02 90 top
